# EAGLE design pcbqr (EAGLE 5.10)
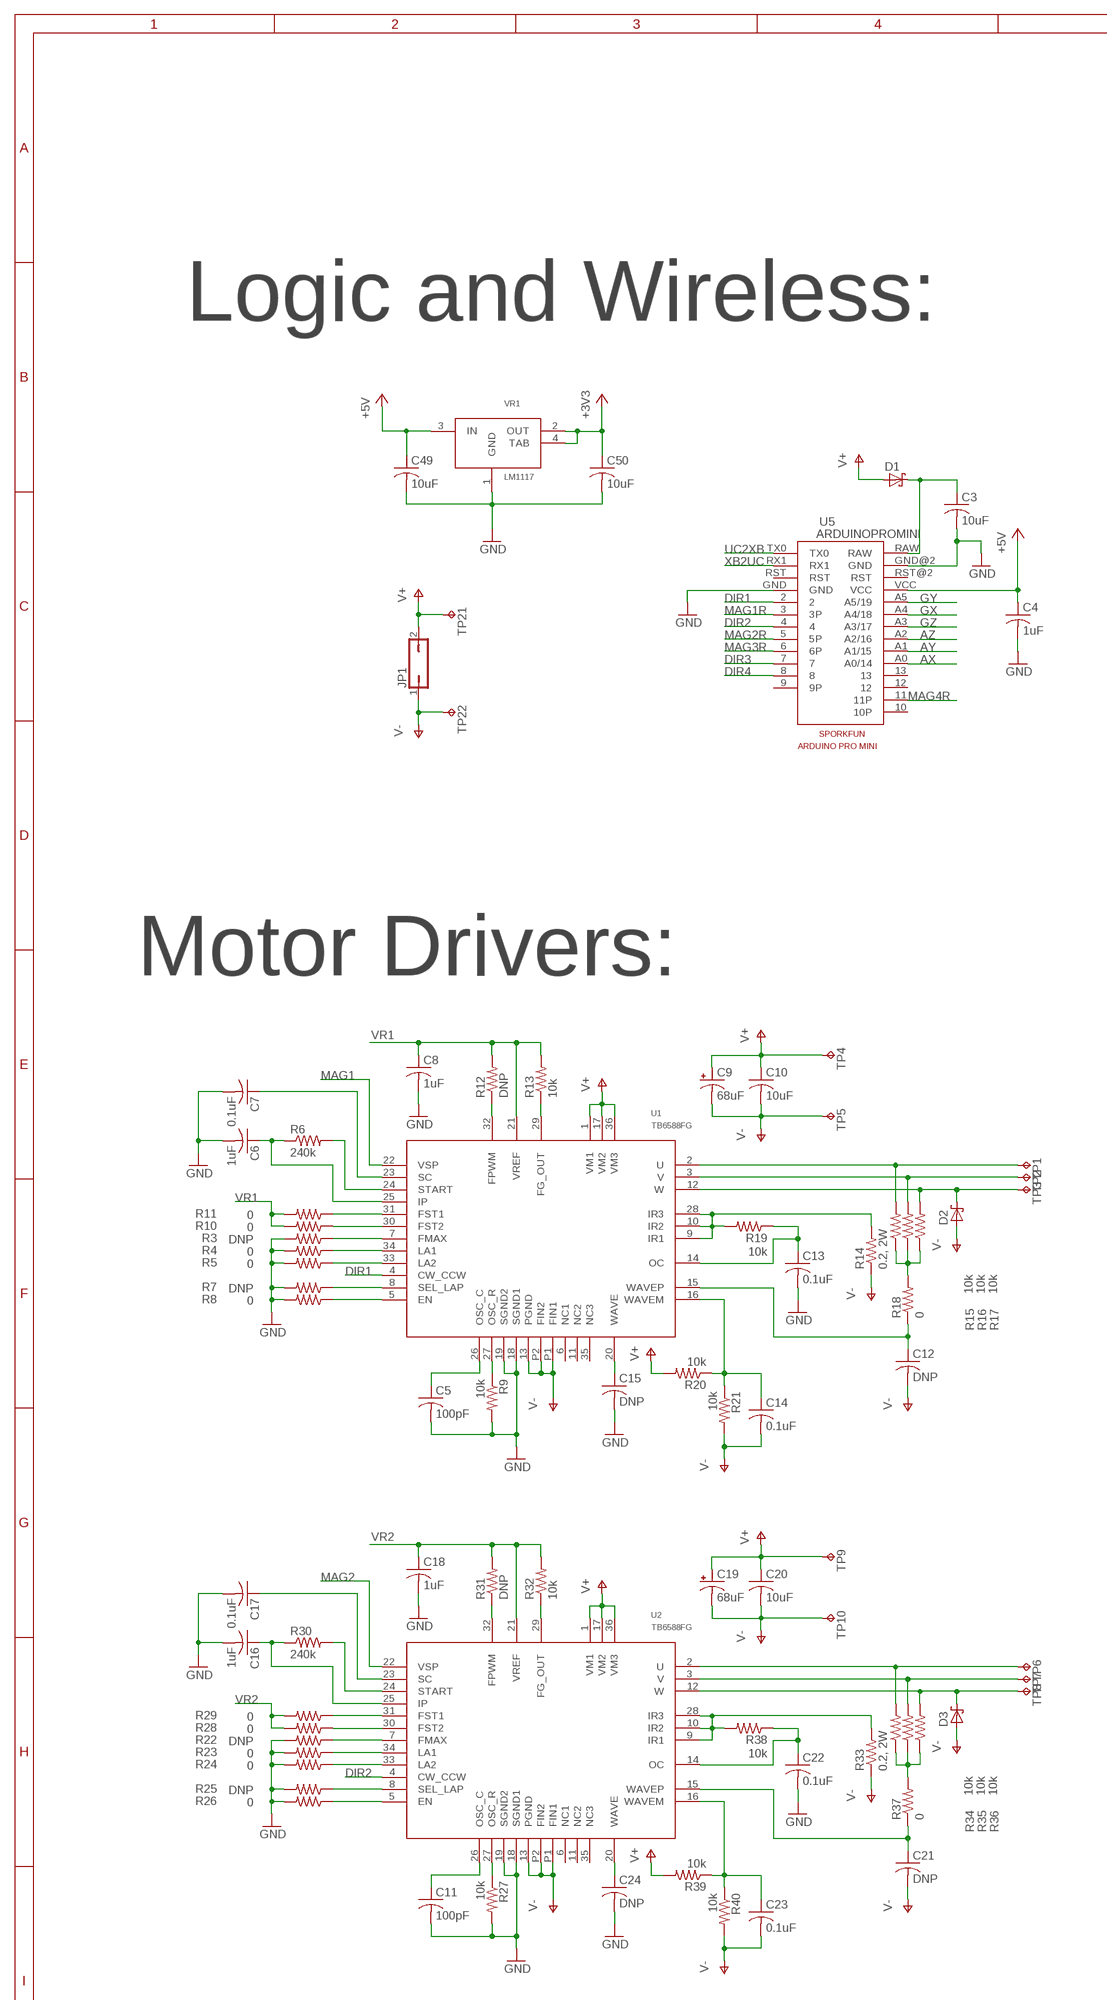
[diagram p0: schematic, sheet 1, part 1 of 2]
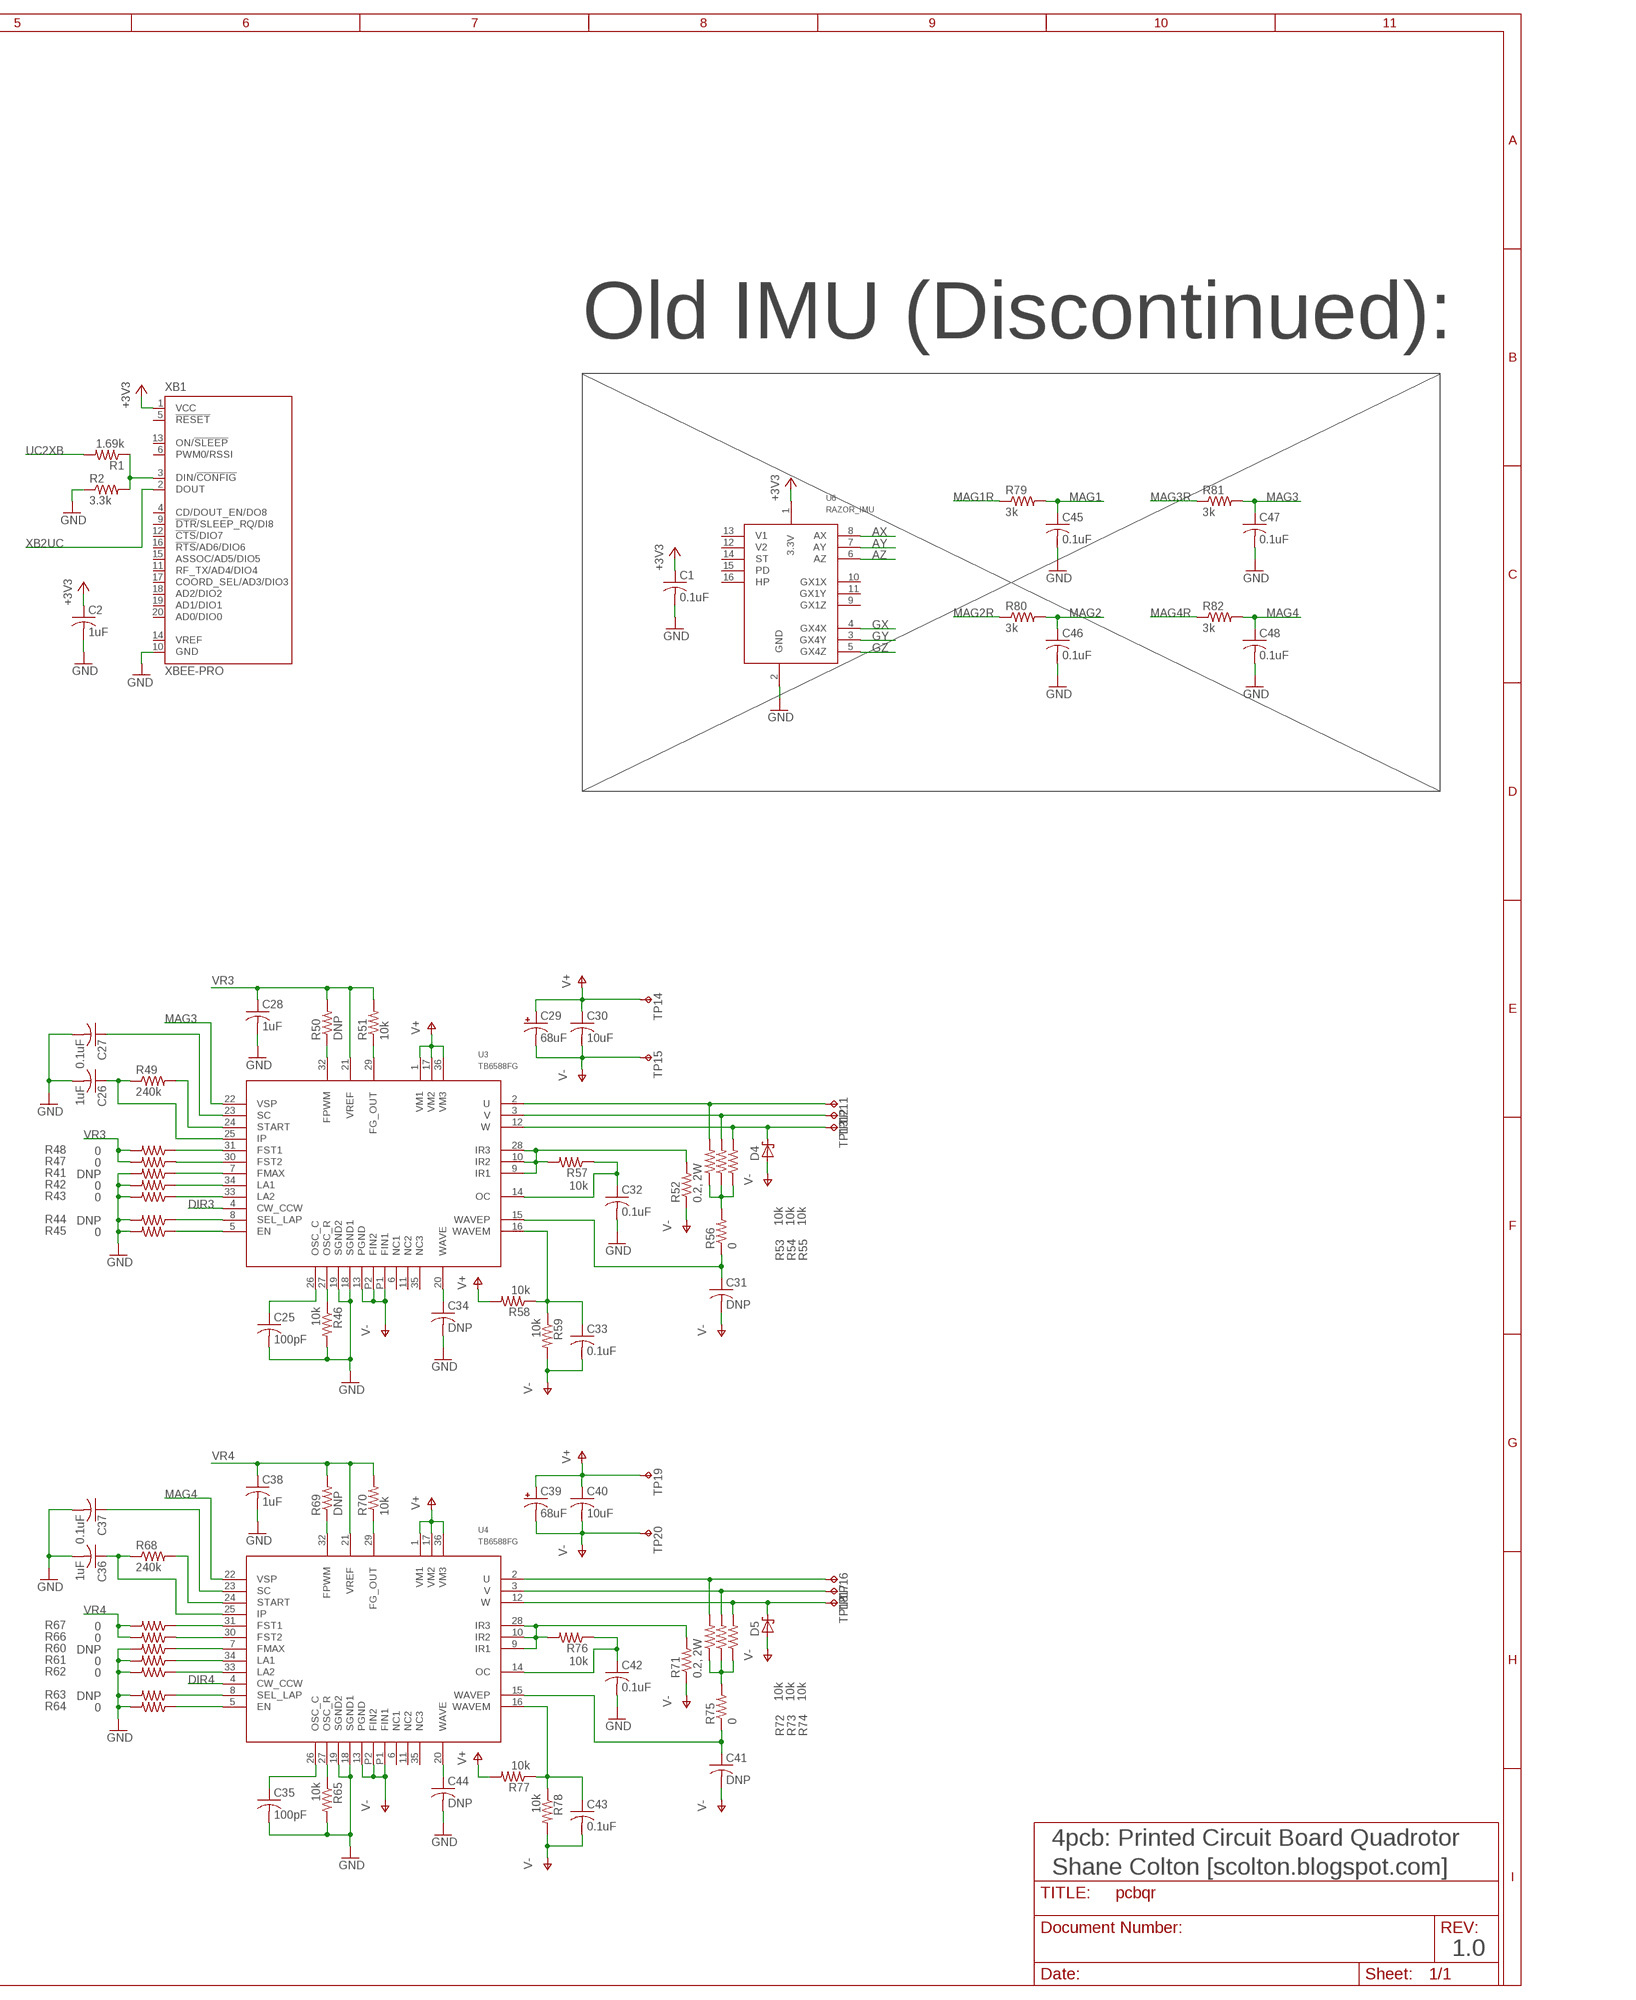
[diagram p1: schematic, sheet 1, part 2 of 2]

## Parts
C1  0.1uF  C-USC0603  [C0603]
C2  1uF  C-USC0603  [C0603]
C3  10uF  C-USC1206  [C1206]
C4  1uF  C-USC0603  [C0603]
C5  100pF  C-USC0603  [C0603]
C6  1uF  C-USC0603  [C0603]
C7  0.1uF  C-USC0603  [C0603]
C8  1uF  C-USC0603  [C0603]
C9  68uF  CPOL-USD  [PANASONIC_D]
C10  10uF  C-USC1206  [C1206]
C11  100pF  C-USC0603  [C0603]
C12  DNP  C-USC0603  [C0603]
C13  0.1uF  C-USC0603  [C0603]
C14  0.1uF  C-USC0603  [C0603]
C15  DNP  C-USC0603  [C0603]
C16  1uF  C-USC0603  [C0603]
C17  0.1uF  C-USC0603  [C0603]
C18  1uF  C-USC0603  [C0603]
C19  68uF  CPOL-USD  [PANASONIC_D]
C20  10uF  C-USC1206  [C1206]
C21  DNP  C-USC0603  [C0603]
C22  0.1uF  C-USC0603  [C0603]
C23  0.1uF  C-USC0603  [C0603]
C24  DNP  C-USC0603  [C0603]
C25  100pF  C-USC0603  [C0603]
C26  1uF  C-USC0603  [C0603]
C27  0.1uF  C-USC0603  [C0603]
C28  1uF  C-USC0603  [C0603]
C29  68uF  CPOL-USD  [PANASONIC_D]
C30  10uF  C-USC1206  [C1206]
C31  DNP  C-USC0603  [C0603]
C32  0.1uF  C-USC0603  [C0603]
C33  0.1uF  C-USC0603  [C0603]
C34  DNP  C-USC0603  [C0603]
C35  100pF  C-USC0603  [C0603]
C36  1uF  C-USC0603  [C0603]
C37  0.1uF  C-USC0603  [C0603]
C38  1uF  C-USC0603  [C0603]
C39  68uF  CPOL-USD  [PANASONIC_D]
C40  10uF  C-USC1206  [C1206]
C41  DNP  C-USC0603  [C0603]
C42  0.1uF  C-USC0603  [C0603]
C43  0.1uF  C-USC0603  [C0603]
C44  DNP  C-USC0603  [C0603]
C45  0.1uF  C-USC0603  [C0603]
C46  0.1uF  C-USC0603  [C0603]
C47  0.1uF  C-USC0603  [C0603]
C48  0.1uF  C-USC0603  [C0603]
C49  10uF  C-USC1206  [C1206]
C50  10uF  C-USC1206  [C1206]
D1  SCHOTTKY_SMA  [SMA]
D2  SCHOTTKY_SMA  [SMA]
D3  SCHOTTKY_SMA  [SMA]
D4  SCHOTTKY_SMA  [SMA]
D5  SCHOTTKY_SMA  [SMA]
JP1  JP1Q  [JP1]
R1  1.69k  R-US_R0603  [R0603]
R2  3.3k  R-US_R0603  [R0603]
R3  DNP  R-US_R0603  [R0603]
R4  0  R-US_R0603  [R0603]
R5  0  R-US_R0603  [R0603]
R6  240k  R-US_R0603  [R0603]
R7  DNP  R-US_R0603  [R0603]
R8  0  R-US_R0603  [R0603]
R9  10k  R-US_R0603  [R0603]
R10  0  R-US_R0603  [R0603]
R11  0  R-US_R0603  [R0603]
R12  DNP  R-US_R0603  [R0603]
R13  10k  R-US_R0603  [R0603]
R14  0.2, 2W  R-US_R2512  [R2512]
R15  10k  R-US_R0603  [R0603]
R16  10k  R-US_R0603  [R0603]
R17  10k  R-US_R0603  [R0603]
R18  0  R-US_R0603  [R0603]
R19  10k  R-US_R0603  [R0603]
R20  10k  R-US_R0603  [R0603]
R21  10k  R-US_R0603  [R0603]
R22  DNP  R-US_R0603  [R0603]
R23  0  R-US_R0603  [R0603]
R24  0  R-US_R0603  [R0603]
R25  DNP  R-US_R0603  [R0603]
R26  0  R-US_R0603  [R0603]
R27  10k  R-US_R0603  [R0603]
R28  0  R-US_R0603  [R0603]
R29  0  R-US_R0603  [R0603]
R30  240k  R-US_R0603  [R0603]
R31  DNP  R-US_R0603  [R0603]
R32  10k  R-US_R0603  [R0603]
R33  0.2, 2W  R-US_R2512  [R2512]
R34  10k  R-US_R0603  [R0603]
R35  10k  R-US_R0603  [R0603]
R36  10k  R-US_R0603  [R0603]
R37  0  R-US_R0603  [R0603]
R38  10k  R-US_R0603  [R0603]
R39  10k  R-US_R0603  [R0603]
R40  10k  R-US_R0603  [R0603]
R41  DNP  R-US_R0603  [R0603]
R42  0  R-US_R0603  [R0603]
R43  0  R-US_R0603  [R0603]
R44  DNP  R-US_R0603  [R0603]
R45  0  R-US_R0603  [R0603]
R46  10k  R-US_R0603  [R0603]
R47  0  R-US_R0603  [R0603]
R48  0  R-US_R0603  [R0603]
R49  240k  R-US_R0603  [R0603]
R50  DNP  R-US_R0603  [R0603]
R51  10k  R-US_R0603  [R0603]
R52  0.2, 2W  R-US_R2512  [R2512]
R53  10k  R-US_R0603  [R0603]
R54  10k  R-US_R0603  [R0603]
R55  10k  R-US_R0603  [R0603]
R56  0  R-US_R0603  [R0603]
R57  10k  R-US_R0603  [R0603]
R58  10k  R-US_R0603  [R0603]
R59  10k  R-US_R0603  [R0603]
R60  DNP  R-US_R0603  [R0603]
R61  0  R-US_R0603  [R0603]
R62  0  R-US_R0603  [R0603]
R63  DNP  R-US_R0603  [R0603]
R64  0  R-US_R0603  [R0603]
R65  10k  R-US_R0603  [R0603]
R66  0  R-US_R0603  [R0603]
R67  0  R-US_R0603  [R0603]
R68  240k  R-US_R0603  [R0603]
R69  DNP  R-US_R0603  [R0603]
R70  10k  R-US_R0603  [R0603]
R71  0.2, 2W  R-US_R2512  [R2512]
R72  10k  R-US_R0603  [R0603]
R73  10k  R-US_R0603  [R0603]
R74  10k  R-US_R0603  [R0603]
R75  0  R-US_R0603  [R0603]
R76  10k  R-US_R0603  [R0603]
R77  10k  R-US_R0603  [R0603]
R78  10k  R-US_R0603  [R0603]
R79  3k  R-US_R0603  [R0603]
R80  3k  R-US_R0603  [R0603]
R81  3k  R-US_R0603  [R0603]
R82  3k  R-US_R0603  [R0603]
TP1  TPTP20SQ  [TP20SQ]
TP2  TPTP20SQ  [TP20SQ]
TP3  TPTP20SQ  [TP20SQ]
TP4  TPTP20SQ  [TP20SQ]
TP5  TPTP20SQ  [TP20SQ]
TP6  TPTP20SQ  [TP20SQ]
TP7  TPTP20SQ  [TP20SQ]
TP8  TPTP20SQ  [TP20SQ]
TP9  TPTP20SQ  [TP20SQ]
TP10  TPTP20SQ  [TP20SQ]
TP11  TPTP20SQ  [TP20SQ]
TP12  TPTP20SQ  [TP20SQ]
TP13  TPTP20SQ  [TP20SQ]
TP14  TPTP20SQ  [TP20SQ]
TP15  TPTP20SQ  [TP20SQ]
TP16  TPTP20SQ  [TP20SQ]
TP17  TPTP20SQ  [TP20SQ]
TP18  TPTP20SQ  [TP20SQ]
TP19  TPTP20SQ  [TP20SQ]
TP20  TPTP20SQ  [TP20SQ]
TP21  TPTP20SQ  [TP20SQ]
TP22  TPTP20SQ  [TP20SQ]
U1  TB6588FG  [HSOP36-P-450-0.65]
U2  TB6588FG  [HSOP36-P-450-0.65]
U3  TB6588FG  [HSOP36-P-450-0.65]
U4  TB6588FG  [HSOP36-P-450-0.65]
U5  ARDUINOPROMINI  [ARDUINO_PRO_MINI]
U6  RAZOR_IMU  [RAZOR_IMU]
VR1  LM1117  [SOT-223]
XB1  XBEE-PRO  [XBEE-PRO]

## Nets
+3V3: C1.1 C2.1 C50.1 U6.1(3.3V) VR1.2(OUT) VR1.4(TAB) XB1.1(VCC)
+5V: C4.1 C49.1 U5.VCC VR1.3(IN)
AX: U5.A0(A0/14) U6.8(AX)
AY: U5.A1(A1/15) U6.7(AY)
AZ: U5.A2(A2/16) U6.6(AZ)
DIR1: U1.4(CW_CCW) U5.2
DIR2: U2.4(CW_CCW) U5.4
DIR3: U3.4(CW_CCW) U5.7
DIR4: U4.4(CW_CCW) U5.8
GND: C1.2 C2.2 C3.2 C4.2 C5.2 C6.2 C7.2 C8.2 C11.2 C13.2 C15.2 C16.2 C17.2 C18.2 C22.2 C24.2 C25.2 C26.2 C27.2 C28.2 C32.2 C34.2 C35.2 C36.2 C37.2 C38.2 C42.2 C44.2 C45.2 C46.2 C47.2 C48.2 C49.2 C50.2 R2.1 R3.2 R4.2 R5.2 R7.2 R8.2 R9.2 R22.2 R23.2 R24.2 R25.2 R26.2 R27.2 R41.2 R42.2 R43.2 R44.2 R45.2 R46.2 R60.2 R61.2 R62.2 R63.2 R64.2 R65.2 U1.18(SGND1) U1.19(SGND2) U2.18(SGND1) U2.19(SGND2) U3.18(SGND1) U3.19(SGND2) U4.18(SGND1) U4.19(SGND2) U5.GND U5.GND@2(GND) U6.2(GND) VR1.1(GND) XB1.10(GND)
GX: U5.A4(A4/18) U6.4(GX4X)
GY: U5.A5(A5/19) U6.3(GX4Y)
GZ: U5.A3(A3/17) U6.5(GX4Z)
MAG1: C45.1 R79.2 U1.22(VSP)
MAG1R: R79.1 U5.3(3P)
MAG2: C46.1 R80.2 U2.22(VSP)
MAG2R: R80.1 U5.5(5P)
MAG3: C47.1 R81.2 U3.22(VSP)
MAG3R: R81.1 U5.6(6P)
MAG4: C48.1 R82.2 U4.22(VSP)
MAG4R: R82.1 U5.11(11P)
N$1: R1.1 R2.2 XB1.3(DIN/!CONFIG)
N$2: C3.1 D1.C U5.RAW
N$3: R15.1 R16.1 R17.1 R18.2
N$4: R14.2 R19.2 U1.9(IR1) U1.10(IR2) U1.28(IR3)
N$5: R15.2 TP1.TP U1.2(U)
N$6: R16.2 TP2.TP U1.3(V)
N$7: D2.C R17.2 TP3.TP U1.12(W)
N$8: R8.1 U1.5(EN)
N$9: R7.1 U1.8(SEL_LAP)
N$10: R6.2 U1.24(START)
N$11: R5.1 U1.33(LA2)
N$12: R4.1 U1.34(LA1)
N$13: R3.1 U1.7(FMAX)
N$14: C5.1 U1.26(OSC_C)
N$15: R9.1 U1.27(OSC_R)
N$16: R10.1 U1.30(FST2)
N$17: R11.1 U1.31(FST1)
N$18: C6.1 R6.1 U1.25(IP)
N$19: R12.1 U1.32(FPWM)
N$20: C7.1 U1.23(SC)
N$21: R13.1 U1.29(FG_OUT)
N$22: C14.1 R20.1 R21.1 U1.16(WAVEM)
N$23: R33.2 R38.2 U2.9(IR1) U2.10(IR2) U2.28(IR3)
N$24: C12.1 R18.1 U1.15(WAVEP)
N$25: C13.1 R19.1 U1.14(OC)
N$26: C15.1 U1.20(WAVE)
N$27: R34.2 TP6.TP U2.2(U)
N$28: R35.2 TP7.TP U2.3(V)
N$29: D3.C R36.2 TP8.TP U2.12(W)
N$30: R26.1 U2.5(EN)
N$31: R25.1 U2.8(SEL_LAP)
N$32: R24.1 U2.33(LA2)
N$33: R23.1 U2.34(LA1)
N$34: R22.1 U2.7(FMAX)
N$35: C11.1 U2.26(OSC_C)
N$36: R27.1 U2.27(OSC_R)
N$37: R28.1 U2.30(FST2)
N$38: R29.1 U2.31(FST1)
N$39: R30.2 U2.24(START)
N$40: C16.1 R30.1 U2.25(IP)
N$41: C17.1 U2.23(SC)
N$42: R31.1 U2.32(FPWM)
N$43: R32.1 U2.29(FG_OUT)
N$44: R34.1 R35.1 R36.1 R37.2
N$45: C21.1 R37.1 U2.15(WAVEP)
N$46: C22.1 R38.1 U2.14(OC)
N$47: C23.1 R39.1 R40.1 U2.16(WAVEM)
N$48: C24.1 U2.20(WAVE)
N$49: R52.2 R57.2 U3.9(IR1) U3.10(IR2) U3.28(IR3)
N$50: R53.2 TP11.TP U3.2(U)
N$51: R54.2 TP12.TP U3.3(V)
N$52: D4.C R55.2 TP13.TP U3.12(W)
N$53: R45.1 U3.5(EN)
N$54: R44.1 U3.8(SEL_LAP)
N$55: R43.1 U3.33(LA2)
N$56: R42.1 U3.34(LA1)
N$57: R41.1 U3.7(FMAX)
N$58: C25.1 U3.26(OSC_C)
N$59: R46.1 U3.27(OSC_R)
N$60: R47.1 U3.30(FST2)
N$61: R48.1 U3.31(FST1)
N$62: R49.2 U3.24(START)
N$63: C26.1 R49.1 U3.25(IP)
N$64: C27.1 U3.23(SC)
N$65: R50.1 U3.32(FPWM)
N$66: R51.1 U3.29(FG_OUT)
N$67: R53.1 R54.1 R55.1 R56.2
N$68: C31.1 R56.1 U3.15(WAVEP)
N$69: C32.1 R57.1 U3.14(OC)
N$70: C33.1 R58.1 R59.1 U3.16(WAVEM)
N$71: C34.1 U3.20(WAVE)
N$72: R71.2 R76.2 U4.9(IR1) U4.10(IR2) U4.28(IR3)
N$73: R72.2 TP16.TP U4.2(U)
N$74: R73.2 TP17.TP U4.3(V)
N$75: D5.C R74.2 TP18.TP U4.12(W)
N$76: R64.1 U4.5(EN)
N$77: R63.1 U4.8(SEL_LAP)
N$78: R62.1 U4.33(LA2)
N$79: R61.1 U4.34(LA1)
N$80: R60.1 U4.7(FMAX)
N$81: C35.1 U4.26(OSC_C)
N$82: R65.1 U4.27(OSC_R)
N$83: R66.1 U4.30(FST2)
N$84: R67.1 U4.31(FST1)
N$85: R68.2 U4.24(START)
N$86: C36.1 R68.1 U4.25(IP)
N$87: C37.1 U4.23(SC)
N$88: R69.1 U4.32(FPWM)
N$89: R70.1 U4.29(FG_OUT)
N$90: R72.1 R73.1 R74.1 R75.2
N$91: C41.1 R75.1 U4.15(WAVEP)
N$92: C42.1 R76.1 U4.14(OC)
N$93: C43.1 R77.1 R78.1 U4.16(WAVEM)
N$94: C44.1 U4.20(WAVE)
UC2XB: R1.2 U5.TX0
V+: C9.+ C10.1 C19.+ C20.1 C29.+ C30.1 C39.+ C40.1 D1.A JP1.2 R20.2 R39.2 R58.2 R77.2 TP4.TP TP9.TP TP14.TP TP19.TP TP21.TP U1.1(VM1) U1.17(VM2) U1.36(VM3) U2.1(VM1) U2.17(VM2) U2.36(VM3) U3.1(VM1) U3.17(VM2) U3.36(VM3) U4.1(VM1) U4.17(VM2) U4.36(VM3)
V-: C9.- C10.2 C12.2 C14.2 C19.- C20.2 C21.2 C23.2 C29.- C30.2 C31.2 C33.2 C39.- C40.2 C41.2 C43.2 D2.A D3.A D4.A D5.A JP1.1 R14.1 R21.2 R33.1 R40.2 R52.1 R59.2 R71.1 R78.2 TP5.TP TP10.TP TP15.TP TP20.TP TP22.TP U1.13(PGND) U1.P1(FIN1) U1.P2(FIN2) U2.13(PGND) U2.P1(FIN1) U2.P2(FIN2) U3.13(PGND) U3.P1(FIN1) U3.P2(FIN2) U4.13(PGND) U4.P1(FIN1) U4.P2(FIN2)
VR1: C8.1 R10.2 R11.2 R12.2 R13.2 U1.21(VREF)
VR2: C18.1 R28.2 R29.2 R31.2 R32.2 U2.21(VREF)
VR3: C28.1 R47.2 R48.2 R50.2 R51.2 U3.21(VREF)
VR4: C38.1 R66.2 R67.2 R69.2 R70.2 U4.21(VREF)
XB2UC: U5.RX1 XB1.2(DOUT)
Unconnected: U1.6(NC1) U1.11(NC2) U1.35(NC3) U2.6(NC1) U2.11(NC2) U2.35(NC3) U3.6(NC1) U3.11(NC2) U3.35(NC3) U4.6(NC1) U4.11(NC2) U4.35(NC3) U5.9(9P) U5.10(10P) U5.12 U5.13 U5.RST U5.RST@2(RST) U6.9(GX1Z) U6.10(GX1X) U6.11(GX1Y) U6.12(V2) U6.13(V1) U6.14(ST) U6.15(PD) U6.16(HP) XB1.4(CD/DOUT_EN/DO8) XB1.5(!RESET) XB1.6(PWM0/RSSI) XB1.9(!DTR!/SLEEP_RQ/DI8) XB1.11(RF_TX/AD4/DIO4) XB1.12(!CTS!/DIO7) XB1.13(ON/!SLEEP) XB1.14(VREF) XB1.15(ASSOC/AD5/DIO5) XB1.16(!RTS!/AD6/DIO6) XB1.17(COORD_SEL/AD3/DIO3) XB1.18(AD2/DIO2) XB1.19(AD1/DIO1) XB1.20(AD0/DIO0)

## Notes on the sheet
- Logic and Wireless:
- Old IMU (Discontinued):
- Motor Drivers:
- 4pcb: Printed Circuit Board Quadrotor
- Shane Colton [scolton.blogspot.com]
- 1.0

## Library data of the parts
C1-C8 C10-C18 C20-C28 C30-C38 C40-C50 = rcl:C-US: CAPACITOR, American symbol
C9 C19 C29 C39 = rcl:CPOL-US: POLARIZED CAPACITOR, American symbol
D1-D5 = sc_usercreated:SCHOTTKY_SMA
JP1 = jumper:JP1Q: JUMPER
R1-R82 = rcl:R-US_: RESISTOR, American symbol
TP1-TP22 = testpad:TP: Test pad
U1-U4 = sc_usercreated:TB6588FG
U5 = charleses_parts_bin:ARDUINOPROMINI: sparkfun arduino pro mini, 5V/16
U6 = sc_usercreated:RAZOR_IMU
VR1 = sc_usercreated:LM1117
XB1 = maxstream:XBEE: XBee (TM) /XBee-PRO(TM) OEM RF Modules Source: MaxStream, Inc. xbee_productmanual.pdf

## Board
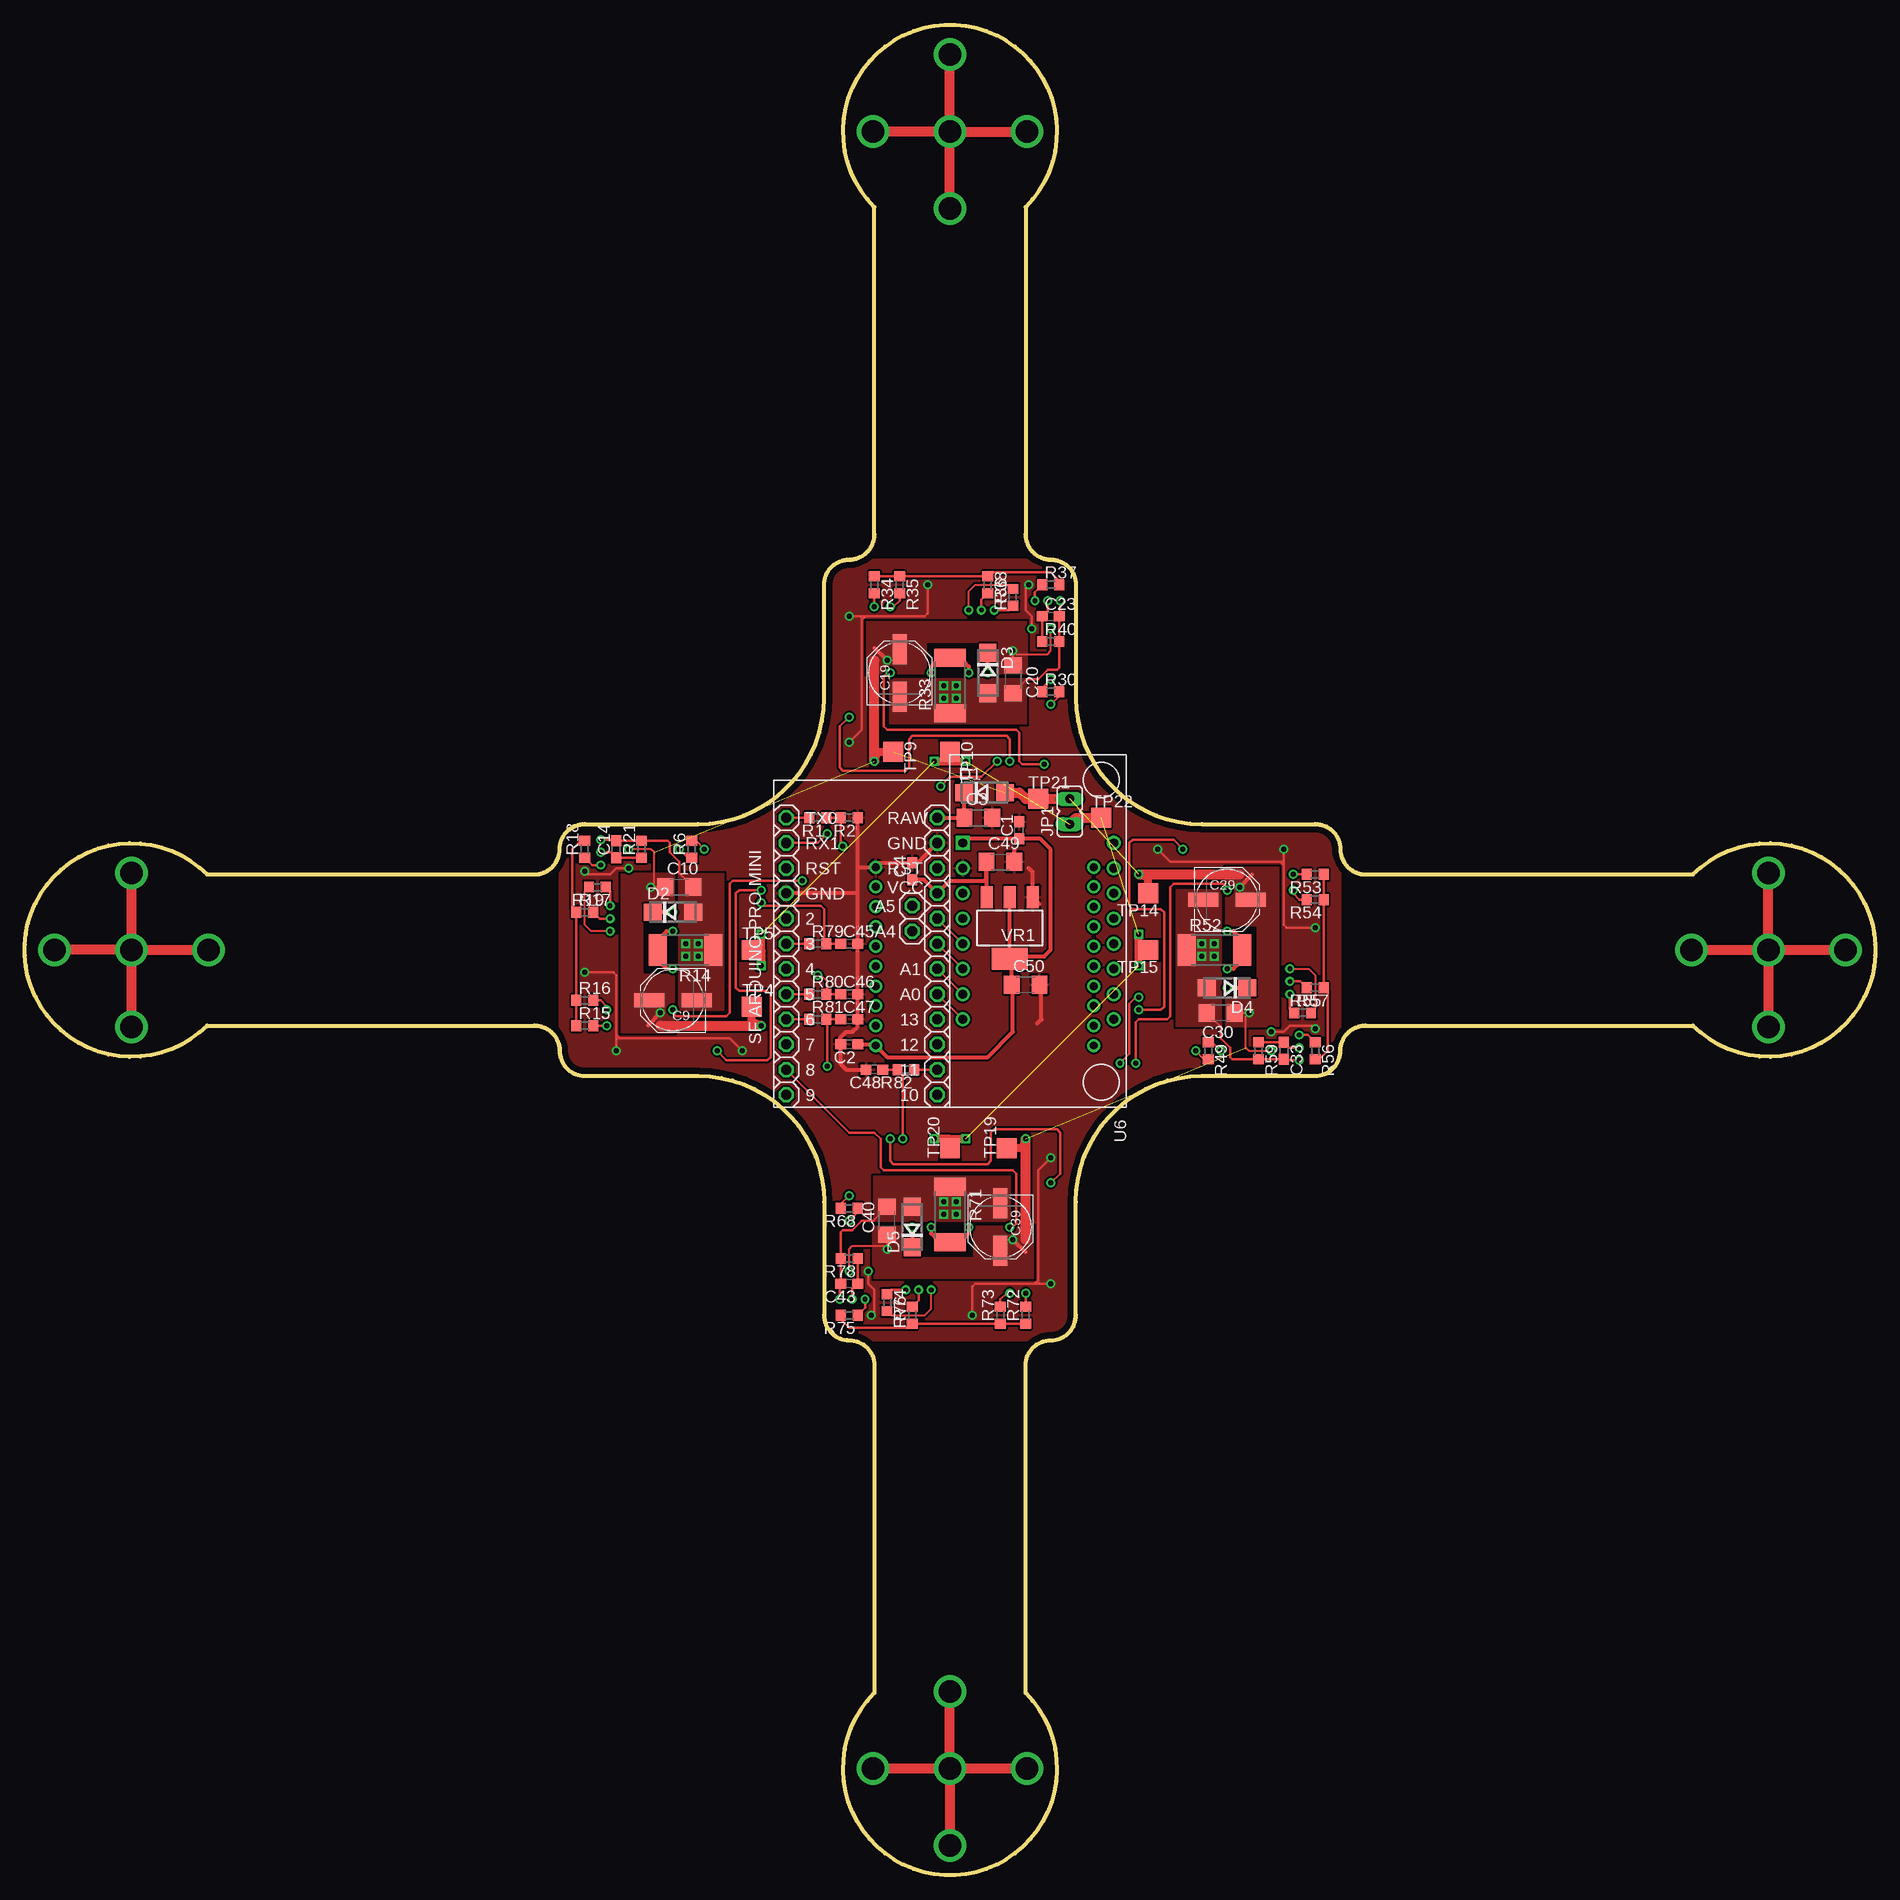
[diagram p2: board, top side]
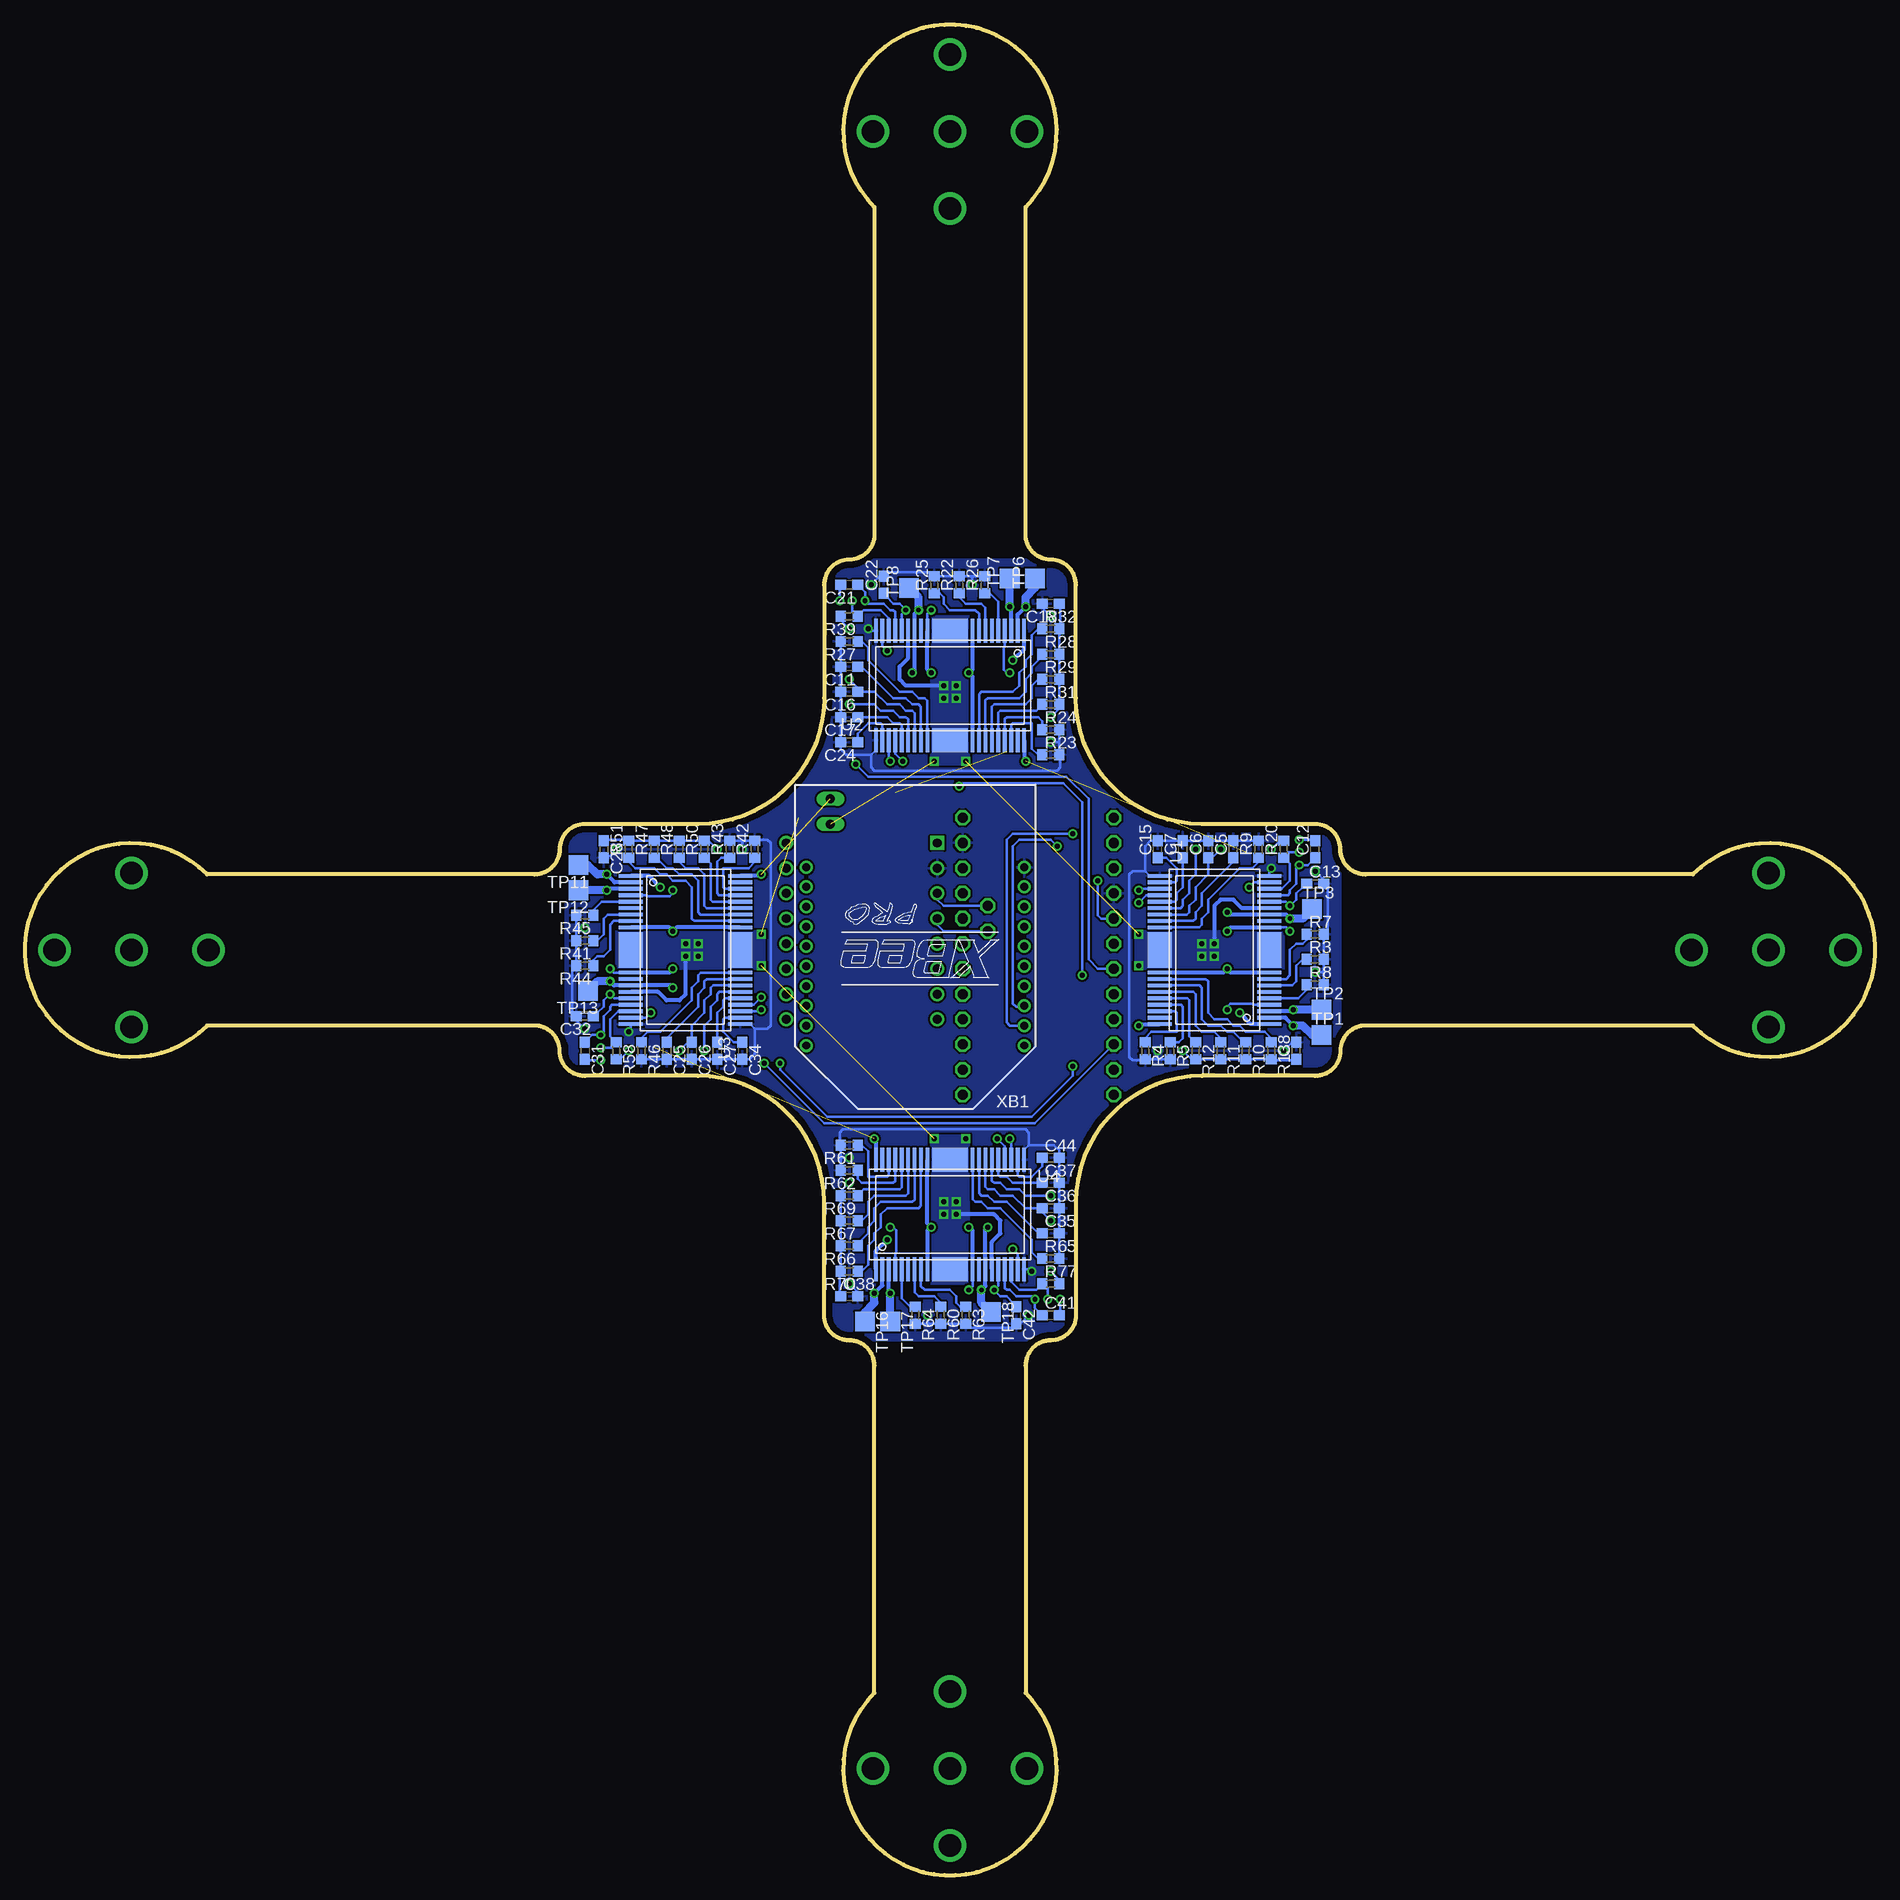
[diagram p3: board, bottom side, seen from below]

Size 186.63 x 186.63 mm. Coordinates in mm from the lower left corner, seen from the top.
Outline: 18.38,100.93 51.4,100.93 arc90 53.94,103.47 arc-90 56.48,106.01 67.91,106.01 arc90 80.61,118.71 80.61,130.14 arc-90 83.15,132.68 arc90 85.69,135.22 85.69,168.24 arc-270 100.93,168.24 100.93,135.22 arc90 103.47,132.68 arc-90 106.01,130.14 106.01,118.71 arc90 118.71,106.01 130.14,106.01 arc-90 132.68,103.47 arc90 135.22,100.93 168.24,100.93 arc-270 168.24,85.69 135.22,85.69 arc90 132.68,83.15 arc-90 130.14,80.61 118.71,80.61 arc90 106.01,67.91 106.01,56.48 arc-90 103.47,53.94 arc90 100.93,51.4 100.93,18.38 arc-270 85.69,18.38 85.69,51.4 arc90 83.15,53.94 arc-90 80.61,56.48 80.61,67.91 arc90 67.91,80.61 56.48,80.61 arc-90 53.94,83.15 arc90 51.4,85.69 18.38,85.69 arc-270 18.38,100.93
Copper layers (1*16): Top 0.035mm / dielectric 1.5mm / Bottom 0.035mm
Design rules "default *": minimum track width 8mil, minimum drill 19mil, track to track 8mil, track to pad 8mil, pad to pad 8mil, via to via 8mil, smd to smd 1mil, copper to edge 25mil, drill to drill 8mil, minimum pad ring 10mil, minimum via ring 8mil, stop-mask expansion 4mil, vias tented up to drill 0mil, thermal gap 10mil

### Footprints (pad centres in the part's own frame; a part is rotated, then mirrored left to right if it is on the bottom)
C0603 = smd 1.1 x 1: 1 -0.85,0; 2 0.85,0
C1206 = smd 1.6 x 1.8: 1 -1.4,0; 2 1.4,0
PANASONIC_D = smd 3 x 1.4: + 2.4,0; - -2.4,0
SMA = smd 1.8 x 1.7: A 2.05,0; C -2.05,0
JP1 = drill 0.914 long: 1 0,-1.27; 2 0,1.27
R0603 = smd 1 x 1.1: 1 -0.85,0; 2 0.85,0
R2512 = smd 1.8 x 3.2: 1 -2.8,0; 2 2.8,0
TP20SQ = smd 2 x 2: TP 0,0
HSOP36-P-450-0.65 = smd 0.38 x 2.4: 1 -7.475,-5.525; 2 -6.825,-5.525; 3 -6.175,-5.525; 4 -5.525,-5.525; 5 -4.875,-5.525; 6 -4.225,-5.525; 7 -3.575,-5.525; 8 -2.925,-5.525; 9 -2.275,-5.525; 10 2.275,-5.525; 11 2.925,-5.525; 12 3.575,-5.525; 13 4.225,-5.525; 14 4.875,-5.525; 15 5.525,-5.525; 16 6.175,-5.525; 17 6.825,-5.525; 18 7.475,-5.525; 19 7.475,5.525; 20 6.825,5.525; 21 6.175,5.525; 22 5.525,5.525; 23 4.875,5.525; 24 4.225,5.525; 25 3.575,5.525; 26 2.925,5.525; 27 2.275,5.525; 28 -2.275,5.525; 29 -2.925,5.525; 30 -3.575,5.525; 31 -4.225,5.525; 32 -4.875,5.525; 33 -5.525,5.525; 34 -6.175,5.525; 35 -6.825,5.525; 36 -7.475,5.525 | smd 3.6 x 2.4: P1 0,-5.525; P2 0,5.525
ARDUINO_PRO_MINI = drill 1.016 octagon: 2 0,17.78; 3 0,15.24; 4 0,12.7; 5 0,10.16; 6 0,7.62; 7 0,5.08; 8 0,2.54; 9 0,0; 10 15.24,0; 11 15.24,2.54; 12 15.24,5.08; 13 15.24,7.62; A0 15.24,10.16; A1 15.24,12.7; A2 15.24,15.24; A3 15.24,17.78; A4 12.7,16.51; A5 12.7,19.05; GND 0,20.32; GND@2 15.24,25.4; RAW 15.24,27.94; RST 0,22.86; RST@2 15.24,22.86; RX1 0,25.4; TX0 0,27.94; VCC 15.24,20.32
RAZOR_IMU = drill 0.9 square: 1 -8.89,-7.62 | drill 0.9 round: 2 -6.35,-7.62; 3 -3.81,-7.62; 4 -1.27,-7.62; 5 1.27,-7.62; 6 3.81,-7.62; 7 6.35,-7.62; 8 8.89,-7.62; 9 8.89,7.62; 10 6.35,7.62; 11 3.81,7.62; 12 1.27,7.62; 13 -1.27,7.62; 14 -3.81,7.62; 15 -6.35,7.62; 16 -8.89,7.62
SOT-223 = smd 1.219 x 2.235: 1 -2.311,-3.099; 2 0,-3.099; 3 2.311,-3.099 | smd 3.6 x 2.2: 4 0,3.099
XBEE-PRO = drill 0.8 pad 1.27 round: 1 -11,9; 2 -11,7; 3 -11,5; 4 -11,3; 5 -11,1; 6 -11,-1; 7 -11,-3; 8 -11,-5; 9 -11,-7; 10 -11,-9; 11 11,-9; 12 11,-7; 13 11,-5; 14 11,-3; 15 11,-1; 16 11,1; 17 11,3; 18 11,5; 19 11,7; 20 11,9

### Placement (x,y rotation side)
C1  100.3,105.38 90 top
C2  83.15,83.79 180 top
C3  96.17,106.65 0 top
C4  89.5,101.25 90 top
C5  64.74,103.47 90 bottom
C6  67.28,103.47 90 bottom
C7  69.82,103.47 90 bottom
C8  58.39,83.15 90 bottom
C9  65.37,88.23 180 top
C10  66.01,99.66 0 top
C11  103.47,121.89 180 bottom
C12  56.48,103.47 90 bottom
C13  56.48,99.98 0 bottom
C14  59.66,103.47 90 top
C15  72.36,103.47 90 bottom
C16  103.47,119.35 180 bottom
C17  103.47,116.81 180 bottom
C18  83.15,128.24 180 bottom
C19  88.23,121.25 90 top
C20  99.66,120.62 270 top
C21  103.47,130.14 180 bottom
C22  99.98,130.14 90 bottom
C23  103.47,126.97 0 top
C24  103.47,114.27 180 bottom
C25  121.89,83.15 270 bottom
C26  119.35,83.15 270 bottom
C27  116.81,83.15 270 bottom
C28  128.24,103.47 270 bottom
C29  121.25,98.39 0 top
C30  120.62,86.96 180 top
C31  130.14,83.15 270 bottom
C32  130.14,86.65 180 bottom
C33  126.97,83.15 270 top
C34  114.27,83.15 270 bottom
C35  83.15,64.74 0 bottom
C36  83.15,67.28 0 bottom
C37  83.15,69.82 0 bottom
C38  103.47,58.39 0 bottom
C39  98.39,65.37 270 top
C40  86.96,66.01 90 top
C41  83.15,56.48 0 bottom
C42  86.65,56.48 270 bottom
C43  83.15,59.66 180 top
C44  83.15,72.36 0 bottom
C45  83.15,93.95 0 top
C46  83.15,88.87 0 top
C47  83.15,86.33 0 top
C48  85.69,81.25 180 top
C49  98.39,102.2 0 top
C50  100.93,89.82 0 top
D1  96.81,109.19 0 top
D2  65.37,97.12 0 top
D3  97.12,121.25 270 top
D4  121.25,89.5 180 top
D5  89.5,65.37 90 top
JP1  105.38,107.28 0 top
R1  79.98,106.65 180 top
R2  83.15,106.65 180 top
R3  56.48,92.36 0 bottom
R4  73.63,83.15 270 bottom
R5  71.09,83.15 270 bottom
R6  67.28,103.47 90 top
R7  56.48,94.9 0 bottom
R8  56.48,89.82 0 bottom
R9  62.2,103.47 90 bottom
R10  63.47,83.15 270 bottom
R11  66.01,83.15 270 bottom
R12  68.55,83.15 270 bottom
R13  60.93,83.15 270 bottom
R14  66.64,93.31 180 top
R15  56.48,85.69 0 top
R16  56.48,88.23 0 top
R17  56.48,97.12 0 top
R18  56.48,103.47 90 top
R19  57.75,99.66 180 top
R20  59.66,103.47 90 bottom
R21  62.2,103.47 90 top
R22  92.36,130.14 90 bottom
R23  83.15,113 0 bottom
R24  83.15,115.54 0 bottom
R25  94.9,130.14 90 bottom
R26  89.82,130.14 90 bottom
R27  103.47,124.43 180 bottom
R28  83.15,123.16 0 bottom
R29  83.15,120.62 0 bottom
R30  103.47,119.35 0 top
R31  83.15,118.08 0 bottom
R32  83.15,125.7 0 bottom
R33  93.31,119.98 90 top
R34  85.69,130.14 270 top
R35  88.23,130.14 270 top
R36  97.12,130.14 270 top
R37  103.47,130.14 0 top
R38  99.66,128.87 90 top
R39  103.47,126.97 180 bottom
R40  103.47,124.43 0 top
R41  130.14,94.27 180 bottom
R42  113,103.47 90 bottom
R43  115.54,103.47 90 bottom
R44  130.14,91.73 180 bottom
R45  130.14,96.81 180 bottom
R46  124.43,83.15 270 bottom
R47  123.16,103.47 90 bottom
R48  120.62,103.47 90 bottom
R49  119.35,83.15 270 top
R50  118.08,103.47 90 bottom
R51  125.7,103.47 90 bottom
R52  119.98,93.31 0 top
R53  130.14,100.93 180 top
R54  130.14,98.39 180 top
R55  130.14,89.5 180 top
R56  130.14,83.15 270 top
R57  128.87,86.96 0 top
R58  126.97,83.15 270 bottom
R59  124.43,83.15 270 top
R60  94.27,56.48 270 bottom
R61  103.47,73.63 180 bottom
R62  103.47,71.09 180 bottom
R63  91.73,56.48 270 bottom
R64  96.81,56.48 270 bottom
R65  83.15,62.2 0 bottom
R66  103.47,63.47 180 bottom
R67  103.47,66.01 180 bottom
R68  83.15,67.28 180 top
R69  103.47,68.55 180 bottom
R70  103.47,60.93 180 bottom
R71  93.31,66.64 270 top
R72  100.93,56.48 90 top
R73  98.39,56.48 90 top
R74  89.5,56.48 90 top
R75  83.15,56.48 180 top
R76  86.96,57.75 270 top
R77  83.15,59.66 0 bottom
R78  83.15,62.2 180 top
R79  79.98,93.95 0 top
R80  79.98,88.87 0 top
R81  79.98,86.33 0 top
R82  88.87,81.25 180 top
TP1  55.85,84.74 0 bottom
TP2  55.85,87.28 0 bottom
TP3  56.8,97.44 0 bottom
TP4  73.31,87.6 0 top
TP5  73.31,93.31 0 top
TP6  84.74,130.78 90 bottom
TP7  87.28,130.78 90 bottom
TP8  97.44,129.83 90 bottom
TP9  87.6,113.32 270 top
TP10  93.31,113.32 270 top
TP11  130.78,101.89 180 bottom
TP12  130.78,99.35 180 bottom
TP13  129.83,89.19 180 bottom
TP14  113.32,99.03 180 top
TP15  113.32,93.31 180 top
TP16  101.89,55.85 270 bottom
TP17  99.35,55.85 270 bottom
TP18  89.19,56.8 270 bottom
TP19  99.03,73.31 90 top
TP20  93.31,73.31 90 top
TP21  102.2,108.55 0 top
TP22  108.55,106.65 0 top
U1  66.64,93.31 90 bottom
U2  93.31,119.98 180 bottom
U3  119.98,93.31 270 bottom
U4  93.31,66.64 0 bottom
U5  76.8,78.71 0 top
U6  102.2,95.22 270 top
VR1  99.35,95.54 180 top
XB1  96.81,92.68 180 bottom

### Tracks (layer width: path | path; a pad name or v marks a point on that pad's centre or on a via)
+3V3
  Top 0.406: VR1.4 99.53,92.25 C50.1 99.66,89.69 99.66,85.06 97.12,82.52 86.96,82.52 XB1.1 85.7,83.79 C2.1 | VR1.4 VR1.2 | VR1.4 99.59,92.68 102.84,92.68 103.47,93.31 103.47,103.47 102.42,104.53 C1.1 95,104.53 U6.1
+5V
  Top 0.406: C4.1 90.67,100.4 U5.VCC 93.31,100.3 96.81,100.3 96.99,100.48 C49.1 96.99,98.68 VR1.3
AX
  Top 0.254: U5.A0 U6.8
AY
  Top 0.254: U5.A1 U6.7
AZ
  Top 0.254: U5.A2 U6.6
DIR1  (via drill 0.5)
  Top 0.254: v65.37,87.28 65.37,86.96 65.69,86.65 70.77,86.65 71.09,86.96 71.09,99.98 71.4,100.3 v78.39,100.3
  Bottom 0.254: U1.4 62.7,87.79 62.83,87.91 65.06,87.91 65.37,87.6 v65.37,87.28 | v78.39,100.3 78.39,96.8 78.07,96.49 U5.2
DIR2  (via drill 0.5)
  Top 0.254: v87.28,121.25 86.96,121.25 86.64,120.94 86.64,115.86 86.96,115.54 99.98,115.54 100.3,115.22 100.3,112.36 100.62,112.04 v102.84,112.04
  Bottom 0.254: U2.4 87.79,123.92 87.92,123.79 87.92,121.57 87.6,121.25 v87.28,121.25 | U5.4 78.39,91.41 79.34,92.36 79.34,108.55 81.56,110.78 101.57,110.78 v102.84,112.04
DIR3  (via drill 0.5)
  Top 0.254: v121.25,99.35 121.25,99.66 120.94,99.98 115.86,99.98 115.54,99.66 115.54,86.65 115.22,86.33 112.36,86.33 112.05,86.01 v112.05,81.88
  Bottom 0.254: U3.4 123.92,98.84 123.79,98.71 121.57,98.71 121.25,99.03 v121.25,99.35 | U5.7 84.74,75.85 106.01,75.85 v112.05,81.88
DIR4  (via drill 0.5)
  Top 0.254: v99.34,65.37 99.66,65.37 99.98,65.69 99.98,70.77 99.66,71.09 86.64,71.09 86.33,71.4 86.33,74.26 85.69,74.9 83.15,74.9 U5.8
  Bottom 0.254: U4.4 98.84,62.7 98.71,62.83 98.71,65.06 99.03,65.37 v99.34,65.37
GND  (via drill 0.5)
  Top 0.254: v60.93,101.57 59.66,101.57 59.02,100.93 56.8,100.93 v56.48,101.25 | 59.66,84.74 59.97,84.42 71.09,84.42 v72.36,83.15 | 59.66,84.74 59.66,90.77 59.34,91.09 v56.48,91.09 | v59.66,83.15 59.66,84.74 | v101.57,125.7 101.57,126.97 100.93,127.6 100.93,129.82 v101.25,130.14 | 84.74,126.97 84.42,126.65 84.42,115.54 v83.15,114.27 | 84.74,126.97 90.77,126.97 91.09,127.29 v91.09,130.14 | 84.74,126.97 v83.15,126.97 | v125.7,85.06 126.97,85.06 127.6,85.69 129.83,85.69 v130.14,85.38 | 126.97,101.89 126.65,102.2 115.54,102.2 v114.27,103.47 | 126.97,101.89 126.97,95.85 127.28,95.54 v130.14,95.54 | 126.97,101.89 v126.97,103.47 | v85.06,60.93 85.06,59.66 85.69,59.02 85.69,56.8 v85.38,56.48 | 101.88,59.66 102.2,59.97 102.2,71.09 v103.47,72.36 | 101.88,59.66 95.85,59.66 95.53,59.34 v95.53,56.48 | 101.88,59.66 v103.47,59.66
  Top 0.406: 84,99.03 C45.2 C46.2 C47.2 84,85.59 83.47,85.06 82.84,85.06 82.2,84.42 82.2,83.89 C2.2 82.3,81.78 82.84,81.25 C48.2 | 84,99.03 84,101.57 | 84,101.57 R2.1 | U5.GND@2 90.03,102.1 C4.2 86.23,102.1 XB1.10 84.11,101.68 84,101.57 | C49.2 99.79,103.34 | 101.25,101.57 101.66,101.16 VR1.1 102.33,97.96 | 102.1,85.91 102.52,86.33 102.52,89.63 C50.2 | 84,99.03 U5.GND
  Bottom 0.254: 55.63,91.09 R8.2 | 55.63,91.09 R3.2 R7.2 55.21,95.22 55.21,99.66 55.32,99.66 C13.2 55.63,100.4 v56.48,101.25 | R9.2 C5.2 C6.2 C7.2 C15.2 73.09,104.32 73.63,103.79 73.63,101.25 | 72.36,82.3 R5.2 70.67,82.3 | 72.36,82.3 R4.2 | U1.18 61.12,101.38 v60.93,101.57 | v56.48,91.09 55.63,91.09 | v72.36,83.15 72.36,82.3 | U1.19 73.17,100.79 73.63,101.25 | 73.63,82.2 74.9,82.2 75.22,82.52 75.22,100.93 74.9,101.25 73.63,101.25 | C8.2 58.81,84 v59.66,83.15 | 91.09,130.99 R26.2 | 91.09,130.99 R22.2 R25.2 95.22,131.41 99.66,131.41 99.66,131.31 C22.2 100.4,130.99 v101.25,130.14 | R27.2 C11.2 C16.2 C17.2 C24.2 104.32,113.53 103.79,113 101.25,113 | 82.3,114.27 R24.2 82.3,115.96 | R23.2 82.3,114.27 | U2.18 101.38,125.51 v101.57,125.7 | v91.09,130.14 91.09,130.99 | 82.3,114.27 v83.15,114.27 | U2.19 100.79,113.46 101.25,113 | 82.2,113 82.2,111.73 82.52,111.41 100.93,111.41 101.25,111.73 101.25,113 | C18.2 84,127.82 v83.15,126.97 | 130.99,95.54 R45.2 | 130.99,95.54 R41.2 R44.2 131.41,91.41 131.41,86.96 131.31,86.96 C32.2 130.99,86.22 v130.14,85.38 | R46.2 C25.2 C26.2 C27.2 C34.2 113.53,82.3 113,82.83 113,85.38 | 114.27,104.32 R43.2 115.96,104.32 | 114.27,104.32 R42.2 | U3.18 125.51,85.25 v125.7,85.06 | 130.99,95.54 v130.14,95.54 | v114.27,103.47 114.27,104.32 | U3.19 113.46,85.84 113,85.38 | 113,104.43 111.73,104.43 111.41,104.11 111.41,85.69 111.73,85.38 113,85.38 | C28.2 127.82,102.62 v126.97,103.47 | 95.53,55.63 R64.2 | 95.53,55.63 R60.2 R63.2 91.41,55.21 86.96,55.21 86.96,55.32 C42.2 86.23,55.63 v85.38,56.48 | R65.2 C35.2 C36.2 C37.2 C44.2 82.3,73.09 82.84,73.63 85.38,73.63 | 104.32,72.36 R62.2 104.32,70.67
  Bottom 0.254: 104.32,72.36 R61.2 | U4.18 85.25,61.12 v85.06,60.93 | 95.53,55.63 v95.53,56.48 | v103.47,72.36 104.32,72.36 | U4.19 85.84,73.17 85.38,73.63 | 104.42,73.63 104.42,74.9 104.11,75.22 85.69,75.22 85.38,74.9 85.38,73.63 | C38.2 102.62,58.81 v103.47,59.66
  pour Bottom (rank 2): 53.94,103.47 53.94,54.2 arc90 54.2,53.94 131.41,53.94 131.79,53.94 arc90 132.05,54.2 132.05,132.68 54.2,132.68 arc90 53.94,132.43
  pour Top (rank 2): 53.94,103.47 53.94,132.68 132.05,132.68 132.68,132.68 132.68,53.94 53.94,53.94
GX
  Bottom 0.254: U6.4 94.58,95.85 93.95,95.22 U5.A4
GY
  Bottom 0.254: U6.3 94.58,98.39 93.95,97.76 U5.A5
GZ
  Top 0.254: U5.A3 U6.5
M1  (via drill 2.26)
  Top 1.016: v10.76,93.31 v10.76,101.08 | v10.76,93.31 10.13,93.31 v2.99,93.31 | v10.76,85.54 v10.76,93.31 | v10.76,93.31 v18.53,93.31
M2  (via drill 2.26)
  Top 1.016: v93.31,175.86 v85.54,175.86 | v93.31,175.86 v93.31,183.63 | 93.95,175.86 v93.31,175.86 | 93.95,175.86 v101.08,175.86 | v93.31,168.09 93.31,175.23 93.95,175.86
M3  (via drill 2.26)
  Top 1.016: v168.09,93.31 175.23,93.31 | 175.23,93.31 v175.86,93.31 175.86,93.95 | 175.86,93.95 v175.86,101.08 | v183.63,93.31 176.5,93.31 175.86,93.95 | v175.86,85.54 175.86,92.68 175.23,93.31
M4  (via drill 2.26)
  Top 1.016: v85.54,10.76 v93.31,10.76 | v93.31,10.76 v93.31,18.53 | v93.31,10.76 v101.08,10.76 | v93.31,10.76 v93.31,2.99
MAG1  (via drill 0.5)
  Top 0.254: C45.1 R79.2 80.61,94.16 80.61,97.44 80.3,97.76 74.58,97.76 v74.26,98.08
  Bottom 0.254: U1.22 73.5,98.84 v74.26,98.08
MAG1R
  Top 0.254: R79.1 U5.3
MAG2  (via drill 0.5)
  Top 0.254: C46.1 R80.2 80.93,88.97 80.93,90.14 80.3,90.77 v79.98,90.77 | v98.07,112.36 96.49,110.78 93.31,110.78 v92.36,109.82
  Bottom 0.254: U2.22 98.84,113.12 v98.07,112.36 | v92.36,109.82 92.04,110.14 81.88,110.14 79.98,108.23 v79.98,90.77
MAG2R
  Top 0.254: R80.1 U5.5
MAG3  (via drill 0.5)
  Top 0.254: C47.1 R81.2 80.93,86.22 v80.93,81.56 | v112.36,88.55 112.05,88.55 111.41,87.91 111.41,82.83 v110.46,81.88
  Bottom 0.254: U3.22 113.13,87.79 v112.36,88.55 | v110.46,81.88 110.46,81.25 105.7,76.49 85.06,76.49 80.93,80.61 v80.93,81.56
MAG3R
  Top 0.254: R81.1 U5.6
MAG4  (via drill 0.5)
  Top 0.254: C48.1 R82.2 88.55,80.72 v88.55,74.26
  Bottom 0.254: U4.22 87.79,73.5 v88.55,74.26
MAG4R
  Top 0.254: R82.1 U5.11
N$1  (via drill 0.5)
  Top 0.254: R1.1 R2.2 82.3,104 v82.52,103.79
  Bottom 0.254: v82.52,103.79 83.15,104.43 86.33,104.43 86.96,103.79 86.96,87.91 86.64,87.6 85.88,87.6 XB1.3
N$2
  Top 0.406: U5.RAW C3.1 94.77,109.17 D1.C
N$3
  Top 0.254: R15.1 R16.1 R17.1 55.21,97.54 55.21,103.47 55.85,104.11 56.27,104.11 R18.2
N$4  (via drill 0.5)
  Top 0.203: v59.02,95.22 57.12,95.22 56.48,95.85 56.48,99.24 R19.2
  Top 0.381: v65.37,95.22 64.74,95.22 64.1,94.58 64.1,93.57 | v65.37,91.41 64.74,91.41 64.1,92.04
  Top 0.406: 64.1,93.57 R14.2 64.1,93.05 64.1,92.04
  Bottom 0.254: U1.10 59.39,95.59 v59.02,95.22
  Bottom 0.381: U1.10 65,95.59 v65.37,95.22 | U1.9 65,91.04 v65.37,91.41 65.74,91.04 U1.28
N$5  (via drill 0.5)
  Top 0.254: v58.7,85.69 R15.2
  Bottom 0.406: U1.2 59.5,86.49 v58.7,85.69
  Bottom 0.813: TP1.TP 56.8,84.74 57.75,85.69 v58.7,85.69
N$6  (via drill 0.5)
  Top 0.254: v58.7,87.28 58.7,87.6 58.07,88.23 R16.2
  Bottom 0.406: U1.3 58.85,87.14 v58.7,87.28
  Bottom 0.813: TP2.TP v58.7,87.28
N$7  (via drill 0.5)
  Top 0.254: v59.02,96.49 57.97,96.49 R17.2
  Top 0.381: v65.37,97.12 D2.C
  Bottom 0.381: U1.12 65.14,96.89 v65.37,97.12
  Bottom 0.406: U1.12 59.42,96.89 v59.02,96.49
  Bottom 0.813: TP3.TP 57.75,96.49 v59.02,96.49
N$8
  Bottom 0.254: U1.5 58.18,88.44 57.33,89.29 R8.1
N$9
  Bottom 0.254: U1.8 59.41,90.39 59.02,90.77 59.02,93.31 58.39,93.95 57.75,93.95 57.33,94.37 R7.1 57.33,95
N$10  (via drill 0.5)
  Top 0.254: v68.55,103.47 67.7,104.32 R6.2
  Bottom 0.254: U1.24 70.04,97.54 69.82,97.76 69.82,98.39 69.18,99.03 69.18,100.3 68.55,100.93 v68.55,103.47
N$11
  Bottom 0.254: U1.33 70.01,87.79 69.82,87.6 69.82,84.42 70.24,84 R5.1
N$12
  Bottom 0.254: U1.34 70.63,87.14 70.45,86.96 70.45,85.06 72.99,85.06 73.63,84.42 R4.1
N$13
  Bottom 0.254: U1.7 58.79,89.74 58.39,90.14 58.39,91.72 57.75,92.36 R3.1
N$14
  Bottom 0.254: U1.26 68.8,96.24 68.55,96.49 68.55,97.12 67.91,97.76 67.91,99.03 64.74,102.2 C5.1
N$15
  Bottom 0.254: U1.27 68.18,95.59 67.91,95.85 67.91,96.49 67.28,97.12 67.28,98.39 64.1,101.57 62.83,101.57 62.2,102.2 R9.1
N$16
  Bottom 0.254: U1.30 68.15,89.74 67.91,89.5 67.91,86.33 67.28,85.69 66.01,85.69 65.37,85.06 64.74,85.06 63.68,84 R10.1
N$17
  Bottom 0.254: U1.31 68.77,89.09 68.55,88.87 68.55,85.69 67.91,85.06 66.64,85.06 66.01,84.42 R11.1
N$18  (via drill 0.5)
  Top 0.254: v66.01,103.47 66.86,102.62 C6.1
  Bottom 0.254: U1.25 69.42,96.89 69.18,97.12 69.18,97.76 68.55,98.39 68.55,99.66 67.28,100.93 C6.1 66.86,102.62 v66.01,103.47
N$19
  Bottom 0.254: U1.32 69.39,88.44 69.18,88.23 69.18,84.64 R12.1
N$20
  Bottom 0.254: U1.23 70.66,98.19 70.45,98.39 70.45,99.03 69.82,99.66 C7.1
N$21
  Bottom 0.254: U1.29 67.53,90.39 67.28,90.14 67.28,86.96 66.64,86.33 65.37,86.33 64.74,85.69 64.1,85.69 63.47,85.06 61.56,85.06 60.93,84.42 R13.1
N$22  (via drill 0.5)
  Top 0.254: R21.1 C14.1 59.12,103.15 v58.07,103.15
  Bottom 0.254: U1.16 59.83,99.49 59.02,100.3 59.02,101.99 C14.1 59.12,103.15 v58.07,103.15
N$23  (via drill 0.5)
  Top 0.203: v95.22,127.6 95.22,129.51 95.85,130.14 99.24,130.14 R38.2
  Top 0.381: v95.22,121.25 95.22,121.89 94.58,122.52 93.57,122.52 | v91.41,121.25 91.41,121.89 92.04,122.52
  Top 0.406: 93.57,122.52 R33.2 93.05,122.52 92.04,122.52
  Bottom 0.254: U2.10 95.59,127.23 v95.22,127.6
  Bottom 0.381: U2.10 95.59,121.62 v95.22,121.25 | U2.9 91.04,121.62 v91.41,121.25 91.04,120.88 U2.28
N$24  (via drill 0.5)
  Top 0.254: C12.1 57.22,101.89 v58.07,101.89
  Bottom 0.254: U1.15 59.21,98.84 59.02,99.03 59.02,99.35 58.39,99.98 58.39,101.57 v58.07,101.89 57.22,101.89 C12.1
N$25  (via drill 0.5)
  Top 0.254: v59.02,97.76 59.02,99.24 R19.1
  Bottom 0.254: U1.14 59.45,98.19 v59.02,97.76 58.39,98.39 58.39,99.03 57.75,99.66 57.65,99.66 C13.1 57.33,100.08
N$26
  Bottom 0.254: U1.20 70.61,100.14 70.45,100.3 70.45,101.57 71.51,102.62 C15.1
N$27  (via drill 0.5)
  Top 0.254: v85.69,127.92 R34.2
  Bottom 0.406: U2.2 86.49,127.13 v85.69,127.92
  Bottom 0.813: TP6.TP 84.74,129.82 85.69,128.87 v85.69,127.92
N$28  (via drill 0.5)
  Top 0.254: v87.28,127.92 87.6,127.92 88.23,128.55 R35.2
  Bottom 0.406: U2.3 87.14,127.78 v87.28,127.92
  Bottom 0.813: v87.28,127.92 TP7.TP
N$29  (via drill 0.5)
  Top 0.254: v96.49,127.6 96.49,128.66 R36.2
  Top 0.381: v97.12,121.25 D3.C
  Bottom 0.381: U2.12 96.89,121.49 v97.12,121.25
  Bottom 0.406: U2.12 96.89,127.2 v96.49,127.6
  Bottom 0.813: TP8.TP 96.49,128.87 v96.49,127.6
N$30
  Bottom 0.254: U2.5 88.44,128.44 89.29,129.29 R26.1
N$31
  Bottom 0.254: U2.8 90.39,127.22 90.77,127.6 93.31,127.6 93.95,128.24 93.95,128.87 94.37,129.29 R25.1 95,129.29
N$32
  Bottom 0.254: U2.33 87.79,116.62 87.6,116.81 84.42,116.81 84,116.39 R24.1
N$33
  Bottom 0.254: U2.34 87.14,116 86.96,116.17 85.06,116.17 85.06,113.63 84.42,113 R23.1
N$34
  Bottom 0.254: U2.7 89.74,127.84 90.14,128.24 91.73,128.24 92.36,128.87 R22.1
N$35
  Bottom 0.254: U2.26 96.24,117.83 96.49,118.08 97.12,118.08 97.76,118.71 99.03,118.71 102.2,121.89 C11.1
N$36
  Bottom 0.254: U2.27 95.59,118.45 95.85,118.71 96.49,118.71 97.12,119.35 98.39,119.35 101.57,122.52 101.57,123.79 102.2,124.43 R27.1
N$37
  Bottom 0.254: U2.30 89.74,118.48 89.5,118.71 86.33,118.71 85.69,119.35 85.69,120.62 85.06,121.25 85.06,121.89 84,122.94 R28.1
N$38
  Bottom 0.254: U2.31 89.09,117.86 88.87,118.08 85.69,118.08 85.06,118.71 85.06,119.98 84.42,120.62 R29.1
N$39  (via drill 0.5)
  Top 0.254: v103.47,118.08 104.32,118.93 R30.2
  Bottom 0.254: U2.24 97.54,116.59 97.76,116.81 98.39,116.81 99.03,117.44 100.3,117.44 100.93,118.08 v103.47,118.08
N$40  (via drill 0.5)
  Top 0.254: v103.47,120.62 102.62,119.77 C16.1
  Bottom 0.254: U2.25 96.89,117.21 97.12,117.44 97.76,117.44 98.39,118.08 99.66,118.08 100.93,119.35 C16.1 102.62,119.77 v103.47,120.62
N$41
  Bottom 0.254: U2.23 98.19,115.97 98.39,116.17 99.03,116.17 99.66,116.81 C17.1
N$42
  Bottom 0.254: U2.32 88.44,117.24 88.23,117.44 84.64,117.44 R31.1
N$43
  Bottom 0.254: U2.29 90.39,119.1 90.14,119.35 86.96,119.35 86.33,119.98 86.33,121.25 85.69,121.89 85.69,122.52 85.06,123.16 85.06,125.06 84.42,125.7 R32.1
N$44
  Top 0.254: R34.1 R35.1 R36.1 97.54,131.41 103.47,131.41 104.11,130.78 104.11,130.36 R37.2
N$45  (via drill 0.5)
  Top 0.254: C21.1 101.88,129.41 v101.88,128.55
  Bottom 0.254: U2.15 98.84,127.41 99.03,127.6 99.34,127.6 99.98,128.24 101.57,128.24 v101.88,128.55 101.88,129.41 C21.1
N$46  (via drill 0.5)
  Top 0.254: v97.76,127.6 99.24,127.6 R38.1
  Bottom 0.254: U2.14 98.19,127.17 v97.76,127.6 98.39,128.24 99.03,128.24 99.66,128.87 99.66,128.97 C22.1 100.08,129.29
N$47  (via drill 0.5)
  Top 0.254: R40.1 C23.1 103.16,127.5 v103.16,128.55
  Bottom 0.254: U2.16 99.49,126.79 100.3,127.6 101.99,127.6 C23.1 103.16,127.5 v103.16,128.55
N$48
  Bottom 0.254: U2.20 100.14,116.01 100.3,116.17 101.57,116.17 102.62,115.12 C24.1
N$49  (via drill 0.5)
  Top 0.203: v127.6,91.41 129.51,91.41 130.14,90.77 130.14,87.38 R57.2
  Top 0.381: v121.25,91.41 121.89,91.41 122.52,92.04 122.52,93.05 | v121.25,95.22 121.89,95.22 122.52,94.58
  Top 0.406: 122.52,93.05 R52.2 122.52,93.57 122.52,94.58
  Bottom 0.254: U3.10 127.23,91.04 v127.6,91.41
  Bottom 0.381: U3.10 121.62,91.04 v121.25,91.41 | U3.9 121.62,95.59 v121.25,95.22 120.88,95.59 U3.28
N$50  (via drill 0.5)
  Top 0.254: v127.92,100.93 R53.2
  Bottom 0.406: U3.2 127.13,100.14 v127.92,100.93
  Bottom 0.813: TP11.TP 129.83,101.89 128.87,100.93 v127.92,100.93
N$51  (via drill 0.5)
  Top 0.254: v127.92,99.35 127.92,99.03 128.55,98.39 R54.2
  Bottom 0.406: U3.3 127.78,99.49 v127.92,99.35
  Bottom 0.813: v127.92,99.35 TP12.TP
N$52  (via drill 0.5)
  Top 0.254: v127.6,90.14 128.66,90.14 R55.2
  Top 0.381: v121.25,89.5 D4.C
  Bottom 0.381: U3.12 121.49,89.74 v121.25,89.5
  Bottom 0.406: U3.12 127.2,89.74 v127.6,90.14
  Bottom 0.813: TP13.TP 128.87,90.14 v127.6,90.14
N$53
  Bottom 0.254: U3.5 128.44,98.19 129.29,97.34 R45.1
N$54
  Bottom 0.254: U3.8 127.22,96.24 127.6,95.85 127.6,93.31 128.24,92.68 128.87,92.68 129.29,92.26 R44.1 129.29,91.62
N$55
  Bottom 0.254: U3.33 116.62,98.84 116.81,99.03 116.81,102.2 116.39,102.62 R43.1
N$56
  Bottom 0.254: U3.34 116,99.49 116.17,99.66 116.17,101.57 113.63,101.57 113,102.2 R42.1
N$57
  Bottom 0.254: U3.7 127.84,96.89 128.24,96.49 128.24,94.9 128.87,94.26 R41.1
N$58
  Bottom 0.254: U3.26 117.83,90.39 118.08,90.14 118.08,89.5 118.71,88.87 118.71,87.6 121.89,84.42 C25.1
N$59
  Bottom 0.254: U3.27 118.45,91.04 118.71,90.77 118.71,90.14 119.35,89.5 119.35,88.23 122.52,85.06 123.79,85.06 124.43,84.42 R46.1
N$60
  Bottom 0.254: U3.30 118.48,96.89 118.71,97.12 118.71,100.3 119.35,100.93 120.62,100.93 121.25,101.57 121.89,101.57 122.94,102.62 R47.1
N$61
  Bottom 0.254: U3.31 117.86,97.54 118.08,97.76 118.08,100.93 118.71,101.57 119.98,101.57 120.62,102.2 R48.1
N$62  (via drill 0.5)
  Top 0.254: v118.08,83.15 118.93,82.3 R49.2
  Bottom 0.254: U3.24 116.59,89.09 116.81,88.87 116.81,88.23 117.44,87.6 117.44,86.33 118.08,85.69 v118.08,83.15
N$63  (via drill 0.5)
  Top 0.254: v120.62,83.15 119.77,84 C26.1
  Bottom 0.254: U3.25 117.21,89.74 117.44,89.5 117.44,88.87 118.08,88.23 118.08,86.96 119.35,85.69 C26.1 119.77,84 v120.62,83.15
N$64
  Bottom 0.254: U3.23 115.97,88.44 116.17,88.23 116.17,87.6 116.81,86.96 C27.1
N$65
  Bottom 0.254: U3.32 117.24,98.19 117.44,98.39 117.44,101.99 R50.1
N$66
  Bottom 0.254: U3.29 119.1,96.24 119.35,96.49 119.35,99.66 119.98,100.3 121.25,100.3 121.89,100.93 122.52,100.93 123.16,101.57 125.06,101.57 125.7,102.2 R51.1
N$67
  Top 0.254: R53.1 R54.1 R55.1 131.41,89.08 131.41,83.15 130.78,82.52 130.36,82.52 R56.2
N$68  (via drill 0.5)
  Top 0.254: C31.1 129.41,84.74 v128.55,84.74
  Bottom 0.254: U3.15 127.41,87.79 127.6,87.6 127.6,87.28 128.24,86.65 128.24,85.06 v128.55,84.74 129.41,84.74 C31.1
N$69  (via drill 0.5)
  Top 0.254: v127.6,88.87 127.6,87.38 R57.1
  Bottom 0.254: U3.14 127.17,88.44 v127.6,88.87 128.24,88.23 128.24,87.6 128.87,86.96 128.97,86.96 C32.1 129.29,86.54
N$70  (via drill 0.5)
  Top 0.254: R59.1 C33.1 127.5,83.47 v128.55,83.47
  Bottom 0.254: U3.16 126.79,87.14 127.6,86.33 127.6,84.64 C33.1 127.5,83.47 v128.55,83.47
N$71
  Bottom 0.254: U3.20 116.01,86.49 116.17,86.33 116.17,85.06 115.12,84 C34.1
N$72  (via drill 0.5)
  Top 0.203: v91.41,59.02 91.41,57.12 90.77,56.48 87.38,56.48 R76.2
  Top 0.381: v91.41,65.37 91.41,64.74 92.04,64.1 93.05,64.1 | v95.22,65.37 95.22,64.74 94.58,64.1
  Top 0.406: 93.05,64.1 R71.2 93.57,64.1 94.58,64.1
  Bottom 0.254: U4.10 91.04,59.39 v91.41,59.02
  Bottom 0.381: U4.10 91.04,65 v91.41,65.37 | U4.9 95.59,65 v95.22,65.37 95.59,65.74 U4.28
N$73  (via drill 0.5)
  Top 0.254: v100.93,58.71 R72.2
  Bottom 0.406: U4.2 100.14,59.5 v100.93,58.71
  Bottom 0.813: TP16.TP 101.88,56.8 100.93,57.75 v100.93,58.71
N$74  (via drill 0.5)
  Top 0.254: v99.34,58.71 99.03,58.71 98.39,58.07 R73.2
  Bottom 0.406: U4.3 99.49,58.85 v99.34,58.71
  Bottom 0.813: TP17.TP v99.34,58.71
N$75  (via drill 0.5)
  Top 0.254: v90.14,59.02 90.14,57.97 R74.2
  Top 0.381: v89.5,65.37 D5.C
  Bottom 0.381: U4.12 89.74,65.14 v89.5,65.37
  Bottom 0.406: U4.12 89.74,59.42 v90.14,59.02
  Bottom 0.813: TP18.TP 90.14,57.75 v90.14,59.02
N$76
  Bottom 0.254: U4.5 98.19,58.18 97.34,57.33 R64.1
N$77
  Bottom 0.254: U4.8 96.24,59.41 95.85,59.02 93.31,59.02 92.68,58.39 92.68,57.75 92.26,57.33 R63.1 91.62,57.33
N$78
  Bottom 0.254: U4.33 98.84,70.01 99.03,69.82 102.2,69.82 102.62,70.24 R62.1
N$79
  Bottom 0.254: U4.34 99.49,70.63 99.66,70.45 101.57,70.45 101.57,72.99 102.2,73.63 R61.1
N$80
  Bottom 0.254: U4.7 96.89,58.79 96.49,58.39 94.9,58.39 94.27,57.75 R60.1
N$81
  Bottom 0.254: U4.26 90.39,68.8 90.14,68.55 89.5,68.55 88.87,67.91 87.6,67.91 84.42,64.74 C35.1
N$82
  Bottom 0.254: U4.27 91.04,68.18 90.77,67.91 90.14,67.91 89.5,67.28 88.23,67.28 85.06,64.1 85.06,62.83 84.42,62.2 R65.1
N$83
  Bottom 0.254: U4.30 96.89,68.15 97.12,67.91 100.3,67.91 100.93,67.28 100.93,66.01 101.57,65.37 101.57,64.74 102.62,63.68 R66.1
N$84
  Bottom 0.254: U4.31 97.54,68.77 97.76,68.55 100.93,68.55 101.57,67.91 101.57,66.64 102.2,66.01 R67.1
N$85  (via drill 0.5)
  Top 0.254: v83.15,68.55 82.3,67.7 R68.2
  Bottom 0.254: U4.24 89.09,70.04 88.87,69.82 88.23,69.82 87.6,69.18 86.33,69.18 85.69,68.55 v83.15,68.55
N$86  (via drill 0.5)
  Top 0.254: v83.15,66.01 84,66.86 C36.1
  Bottom 0.254: U4.25 89.74,69.42 89.5,69.18 88.87,69.18 88.23,68.55 86.96,68.55 85.69,67.28 C36.1 84,66.86 v83.15,66.01
N$87
  Bottom 0.254: U4.23 88.44,70.66 88.23,70.45 87.6,70.45 86.96,69.82 C37.1
N$88
  Bottom 0.254: U4.32 98.19,69.39 98.39,69.18 101.99,69.18 R69.1
N$89
  Bottom 0.254: U4.29 96.24,67.53 96.49,67.28 99.66,67.28 100.3,66.64 100.3,65.37 100.93,64.74 100.93,64.1 101.57,63.47 101.57,61.56 102.2,60.93 R70.1
N$90
  Top 0.254: R72.1 R73.1 R74.1 89.08,55.21 83.15,55.21 82.52,55.85 82.52,56.27 R75.2
N$91  (via drill 0.5)
  Top 0.254: C41.1 84.74,57.22 v84.74,58.07
  Bottom 0.254: U4.15 87.79,59.21 87.6,59.02 87.28,59.02 86.64,58.39 85.06,58.39 v84.74,58.07 84.74,57.22 C41.1
N$92  (via drill 0.5)
  Top 0.254: v88.87,59.02 87.38,59.02 R76.1
  Bottom 0.254: U4.14 88.44,59.45 v88.87,59.02 88.23,58.39 87.6,58.39 86.96,57.75 86.96,57.65 C42.1 86.54,57.33
N$93  (via drill 0.5)
  Top 0.254: R78.1 C43.1 83.47,59.13 v83.47,58.07
  Bottom 0.254: U4.16 87.14,59.83 86.33,59.02 84.64,59.02 C43.1 83.47,59.13 v83.47,58.07
N$94
  Bottom 0.254: U4.20 86.49,70.61 86.33,70.45 85.06,70.45 84,71.51 C44.1
UC2XB
  Top 0.254: U5.TX0 R1.2
V+  (via drill 0.5)  (4 unrouted)
  Top 0.203: v60.93,103.47 63.15,103.47 63.47,103.15 63.47,99.98 v63.15,99.66 | v103.47,125.7 103.47,123.47 103.16,123.16 99.98,123.16 v99.66,123.47 | v125.7,83.15 123.47,83.15 123.16,83.47 123.16,86.65 v123.47,86.96 | v83.15,60.93 83.15,63.15 83.47,63.47 86.64,63.47 v86.96,63.15
  Top 0.254: v63.15,99.66 C10.1 | C20.1 v99.66,123.47 | v123.47,86.96 C30.1 | v86.96,63.15 C40.1
  Top 0.381: C9.+ 63.47,87.74 | v64.1,86.96 62.83,85.69 | C19.+ 87.74,123.16 | v86.96,122.52 85.69,123.79 | C29.+ 123.16,98.89 | v122.52,99.66 123.79,100.93 | C39.+ 98.89,63.47 | v99.66,64.1 100.93,62.83
  Top 0.813: TP4.TP 73.31,85.84 73.45,86.01 v74.26,85.69 | TP9.TP 85.84,113.32 86.01,113.17 v85.69,112.36 | TP14.TP 113.31,100.79 113.17,100.61 v112.36,100.93 | TP19.TP 100.79,73.31 100.62,73.45 v100.93,74.26
  Top 1.016: 64.1,85.69 v74.26,85.69 | v85.69,112.36 85.69,122.52 | v112.36,100.93 122.52,100.93 | 100.93,64.1 v100.93,74.26 | JP1.2 TP21.TP 100.93,108.55 100.3,109.19 D1.A
  Bottom 0.254: U1.17 62.67,100.14 v63.15,99.66 | R20.2 60.08,104.32 v60.93,103.47 | U2.17 100.14,123.95 v99.66,123.47 | R39.2 104.32,126.55 v103.47,125.7 | U3.17 123.95,86.49 v123.47,86.96 | R58.2 126.55,82.3 v125.7,83.15 | U4.17 86.49,62.67 v86.96,63.15 | R77.2 82.3,60.08 v83.15,60.93
  Bottom 0.381: U1.36 74.12,85.84 v74.26,85.69 | U1.1 62.98,85.84 v64.1,86.96 | U2.36 85.84,112.51 v85.69,112.36 | U2.1 85.84,123.65 v86.96,122.52 | U3.36 112.51,100.79 v112.36,100.93 | U3.1 123.65,100.79 v122.52,99.66 | U4.36 100.79,74.12 v100.93,74.26 | U4.1 100.79,62.98 v99.66,64.1
  pour Top (no thermals): 65.37,85.06 60.29,85.06 60.29,100.93 65.37,100.93 65.37,98.39 62.2,98.39 62.2,90.77 65.37,90.77
  pour Top (no thermals): 85.06,121.25 85.06,126.33 100.93,126.33 100.93,121.25 98.39,121.25 98.39,124.43 90.77,124.43 90.77,121.25
  pour Top (no thermals): 121.25,101.57 126.33,101.57 126.33,85.69 121.25,85.69 121.25,88.23 124.43,88.23 124.43,95.85 121.25,95.85
  pour Top (no thermals): 101.57,65.37 101.57,60.29 85.69,60.29 85.69,65.37 88.23,65.37 88.23,62.2 95.85,62.2 95.85,65.37
V-  (via drill 0.5)  (4 unrouted)
  Top 0.254: v58.07,104.43 59.56,104.43 arc-90 C14.2 R21.2 64.84,104.32 65.06,104.11 65.06,103.15 66.01,102.2 66.01,101.06 C10.2 | v104.42,128.55 104.42,127.07 arc-90 C23.2 R40.2 104.32,121.79 104.11,121.57 103.16,121.57 102.2,120.62 101.06,120.62 C20.2 | v128.55,82.2 127.07,82.2 arc-90 C33.2 R59.2 121.78,82.3 121.57,82.52 121.57,83.47 120.62,84.42 120.62,85.56 C30.2 | v82.2,58.07 82.2,59.55 arc-90 C43.2 R78.2 82.3,64.84 82.52,65.06 83.47,65.06 84.42,66.01 85.56,66.01 C40.2
  Top 0.813: 74.26,93.31 v74.26,91.72 | 74.26,93.31 v74.26,94.9 | TP5.TP 74.26,93.31 | v91.73,112.36 93.31,112.36 | 93.31,112.36 v94.9,112.36 | 93.31,112.36 TP10.TP | 112.36,93.31 v112.36,94.9 | v112.36,91.72 112.36,93.31 | 112.36,93.31 TP15.TP | 93.31,74.26 v94.9,74.26 | 93.31,74.26 v91.73,74.26 | TP20.TP 93.31,74.26
  Top 1.016: JP1.1 106.01,106.65 TP22.TP
  Bottom 0.254: C12.2 56.9,104.32 57.01,104.43 v58.07,104.43 | C21.2 104.32,129.72 104.42,129.62 v104.42,128.55 | C31.2 129.72,82.3 129.62,82.2 v128.55,82.2 | C41.2 82.3,56.9 82.2,57 v82.2,58.07
  Bottom 0.381: U1.13 63.88,97.54 64.74,98.39 66.01,98.39 66.64,97.76 v66.64,93.95 | U2.13 97.54,122.74 98.39,121.89 98.39,120.62 97.76,119.98 v93.95,119.98 | U3.13 122.74,89.09 121.89,88.23 120.62,88.23 119.98,88.87 v119.98,92.68 | U4.13 89.09,63.88 88.23,64.74 88.23,66.01 88.87,66.64 v92.68,66.64
  other vias: 66.64,92.68 67.91,92.68 67.91,93.95 92.68,119.98 92.68,118.71 93.95,118.71 119.98,93.95 118.71,93.95 118.71,92.68 93.95,66.64 93.95,67.91 92.68,67.91
  pour Bottom (no thermals): 59.66,95.22 74.58,95.22 74.58,91.41 59.66,91.41
  pour Top (no thermals): 66.01,100.93 66.01,87.28 70.45,87.28 70.45,100.93
  pour Bottom (no thermals): 95.22,126.97 95.22,112.05 91.41,112.05 91.41,126.97
  pour Top (no thermals): 100.93,120.62 87.28,120.62 87.28,116.17 100.93,116.17
  pour Bottom (no thermals): 126.97,91.41 112.05,91.41 112.05,95.22 126.97,95.22
  pour Top (no thermals): 120.62,85.69 120.62,99.35 116.17,99.35 116.17,85.69
  pour Bottom (no thermals): 91.41,59.66 91.41,74.58 95.22,74.58 95.22,59.66
  pour Top (no thermals): 85.69,66.01 99.35,66.01 99.35,70.45 85.69,70.45
VR1  (via drill 0.5)
  Top 0.254: v69.82,83.15 70.77,82.2 74.9,82.2 75.22,82.52 75.22,88.87 74.9,89.18 72.04,89.18 71.72,89.5 71.72,99.03 72.04,99.35 v74.26,99.35
  Bottom 0.254: v69.82,83.15 68.97,82.3 R12.2 R11.2 R10.2 R13.2 60.83,82.2 58.39,82.2 C8.1 | v74.26,99.35 74.12,99.49 U1.21
VR2  (via drill 0.5)
  Top 0.254: v83.15,116.81 82.2,115.86 82.2,111.73 82.52,111.41 88.87,111.41 89.19,111.73 89.19,114.58 89.5,114.9 99.03,114.9 99.34,114.58 v99.34,112.36
  Bottom 0.254: v83.15,116.81 82.3,117.66 R31.2 R29.2 R28.2 R32.2 82.2,125.8 82.2,128.24 C18.1 | v99.34,112.36 99.49,112.5 U2.21
VR3  (via drill 0.5)
  Top 0.254: v116.81,103.47 115.86,104.43 111.73,104.43 111.41,104.11 111.41,97.76 111.73,97.44 114.58,97.44 114.9,97.12 114.9,87.6 114.58,87.28 v112.36,87.28
  Bottom 0.254: v116.81,103.47 117.66,104.32 R50.2 R48.2 R47.2 R51.2 125.8,104.43 128.24,104.43 C28.1 | v112.36,87.28 112.5,87.14 U3.21
VR4  (via drill 0.5)
  Top 0.254: v103.47,69.82 104.42,70.77 104.42,74.9 104.11,75.22 97.76,75.22 97.44,74.9 97.44,72.04 97.12,71.72 87.6,71.72 87.28,72.04 v87.28,74.26
  Bottom 0.254: v103.47,69.82 104.32,68.97 R69.2 R67.2 R66.2 R70.2 104.42,60.83 104.42,58.39 C38.1 | v87.28,74.26 87.14,74.12 U4.21
XB2UC  (via drill 0.5)
  Top 0.254: U5.RX1 79.98,104.11 v80.93,105.06
  Bottom 0.254: v80.93,105.06 86.96,105.06 87.6,104.43 87.6,86.01 87.28,85.69 85.82,85.69 XB1.2

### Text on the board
tDocu: 4pcb | v1.0 | 8-12-11 | scolton.blogspot.com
